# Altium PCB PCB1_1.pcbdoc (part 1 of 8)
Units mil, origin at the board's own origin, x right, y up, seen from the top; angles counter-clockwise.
Board outline 3937.01 x 3346.46 mil, 6 copper layers (Top Layer, Signal-1, SIG, POWER, Signal-4, Bottom Layer), stack 60.565 mil thick; 256 components, 201 nets, 1360 pads, 815 vias.
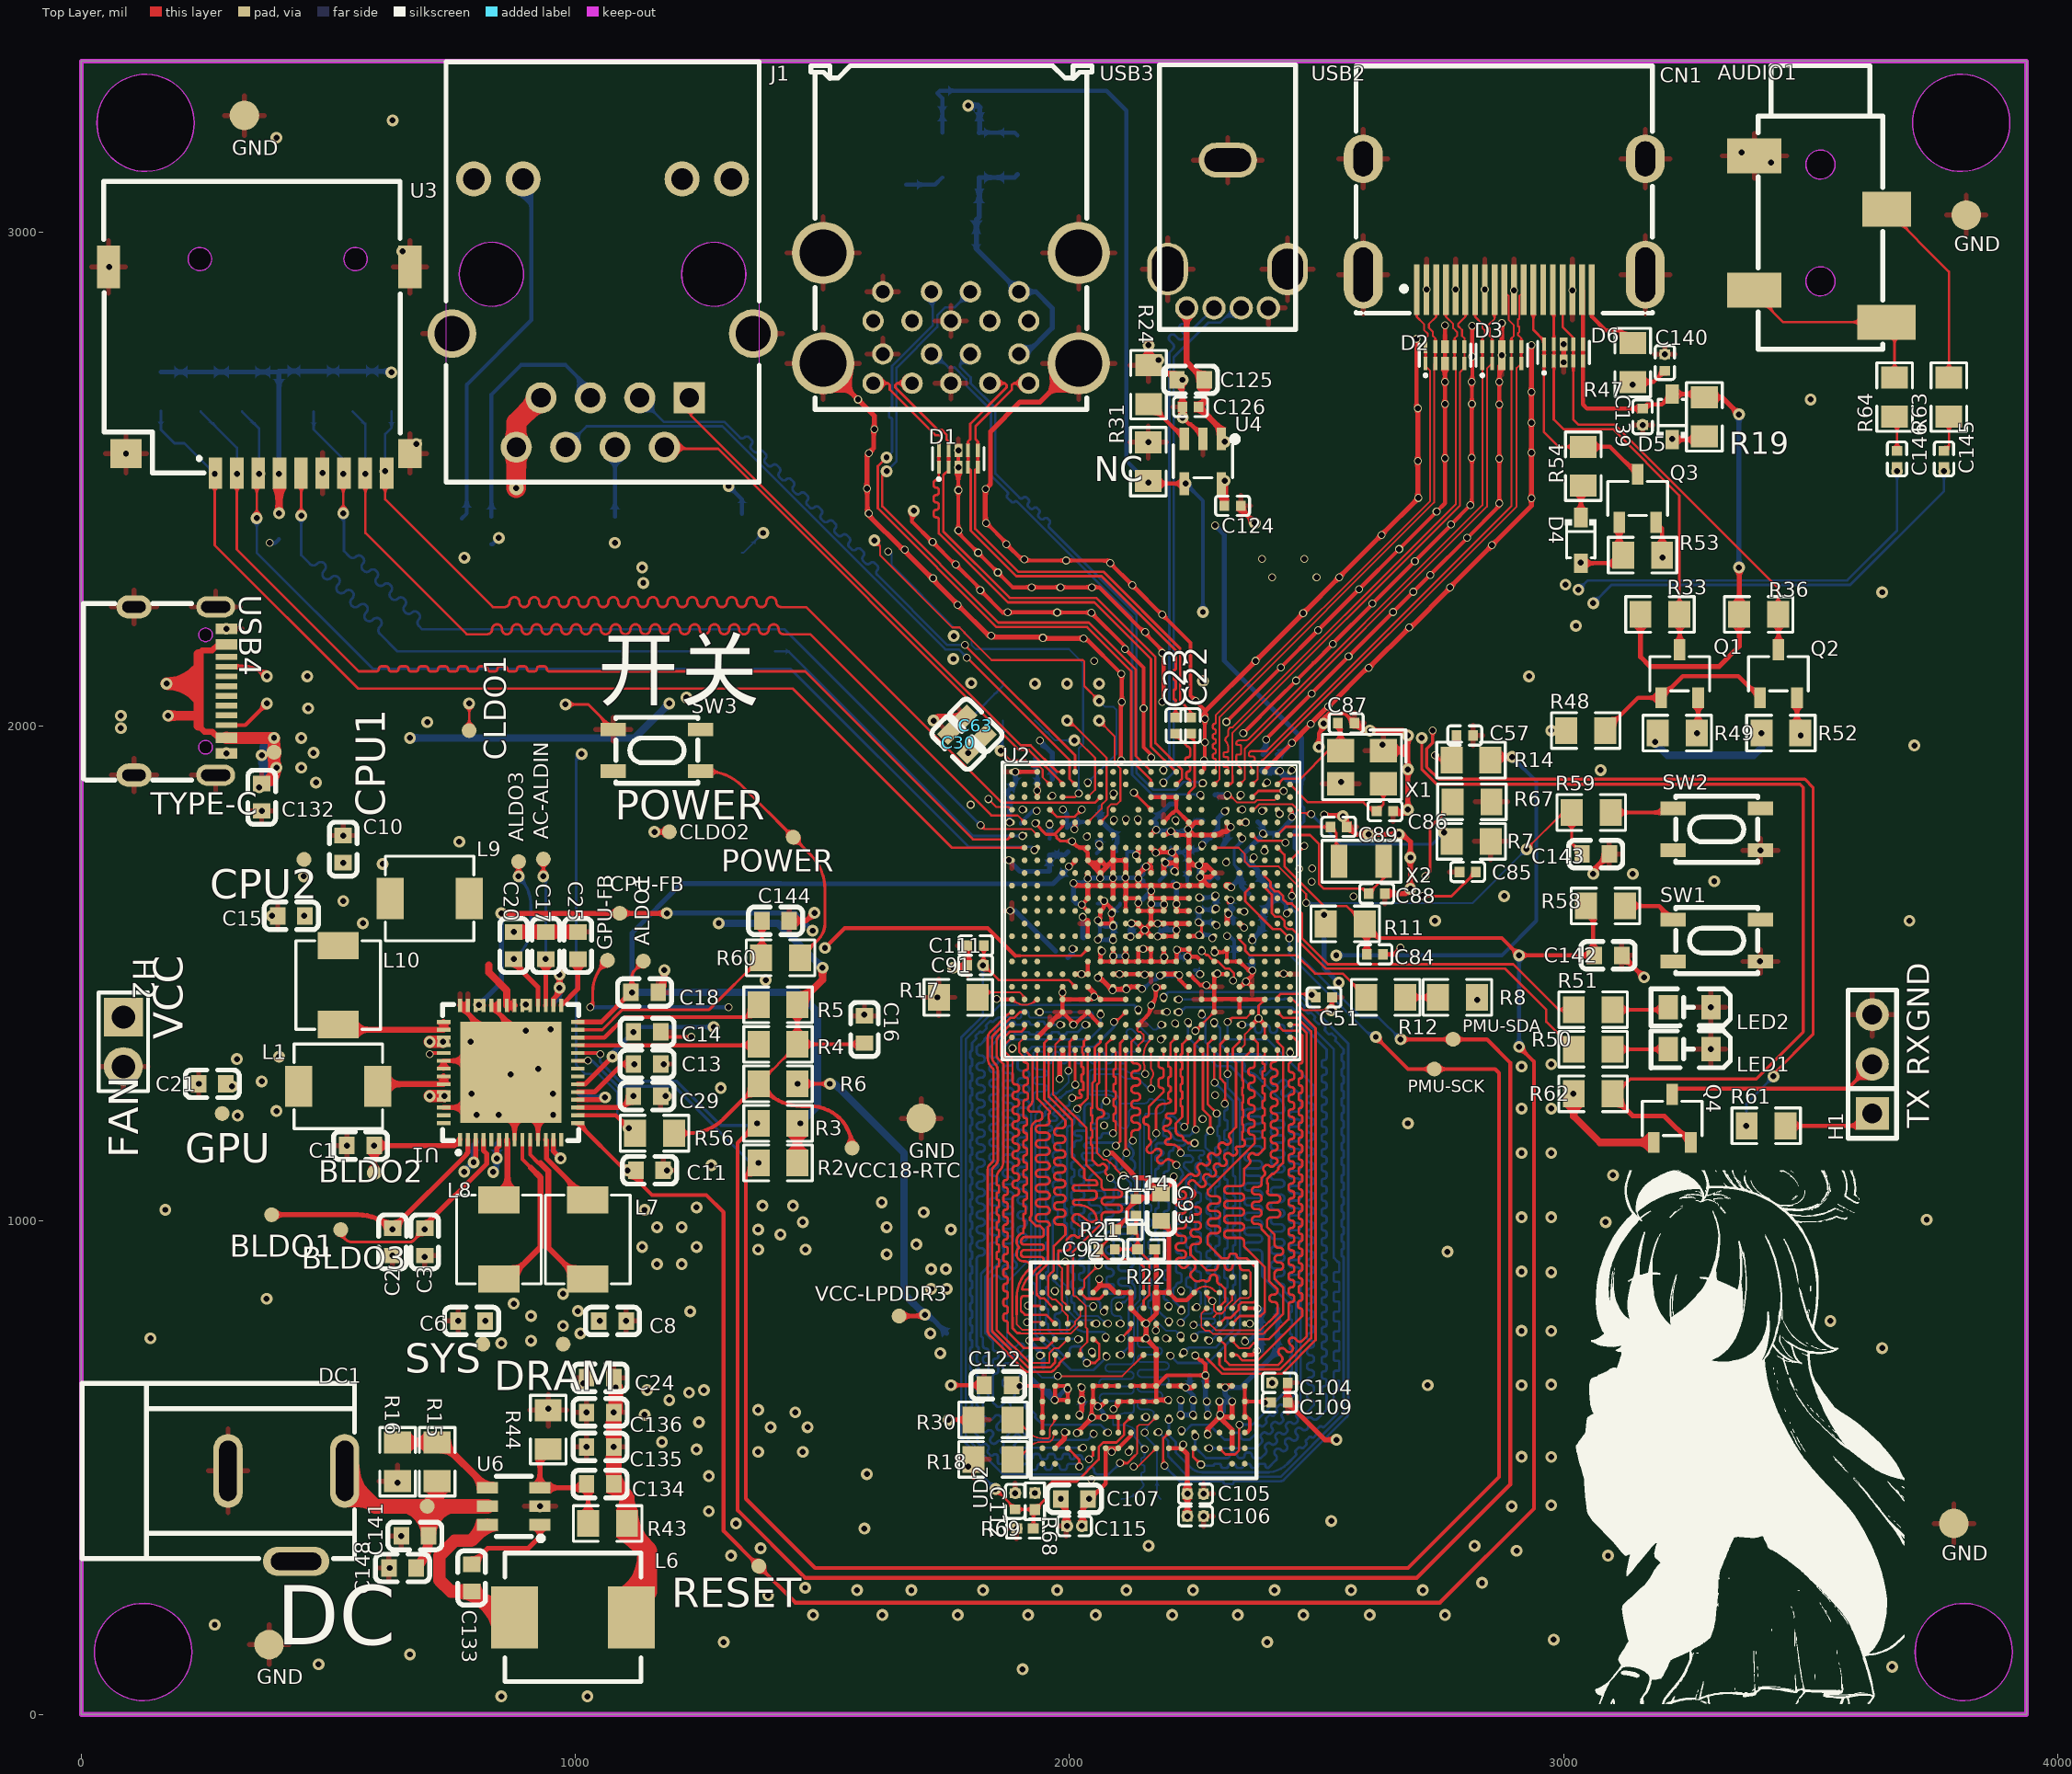
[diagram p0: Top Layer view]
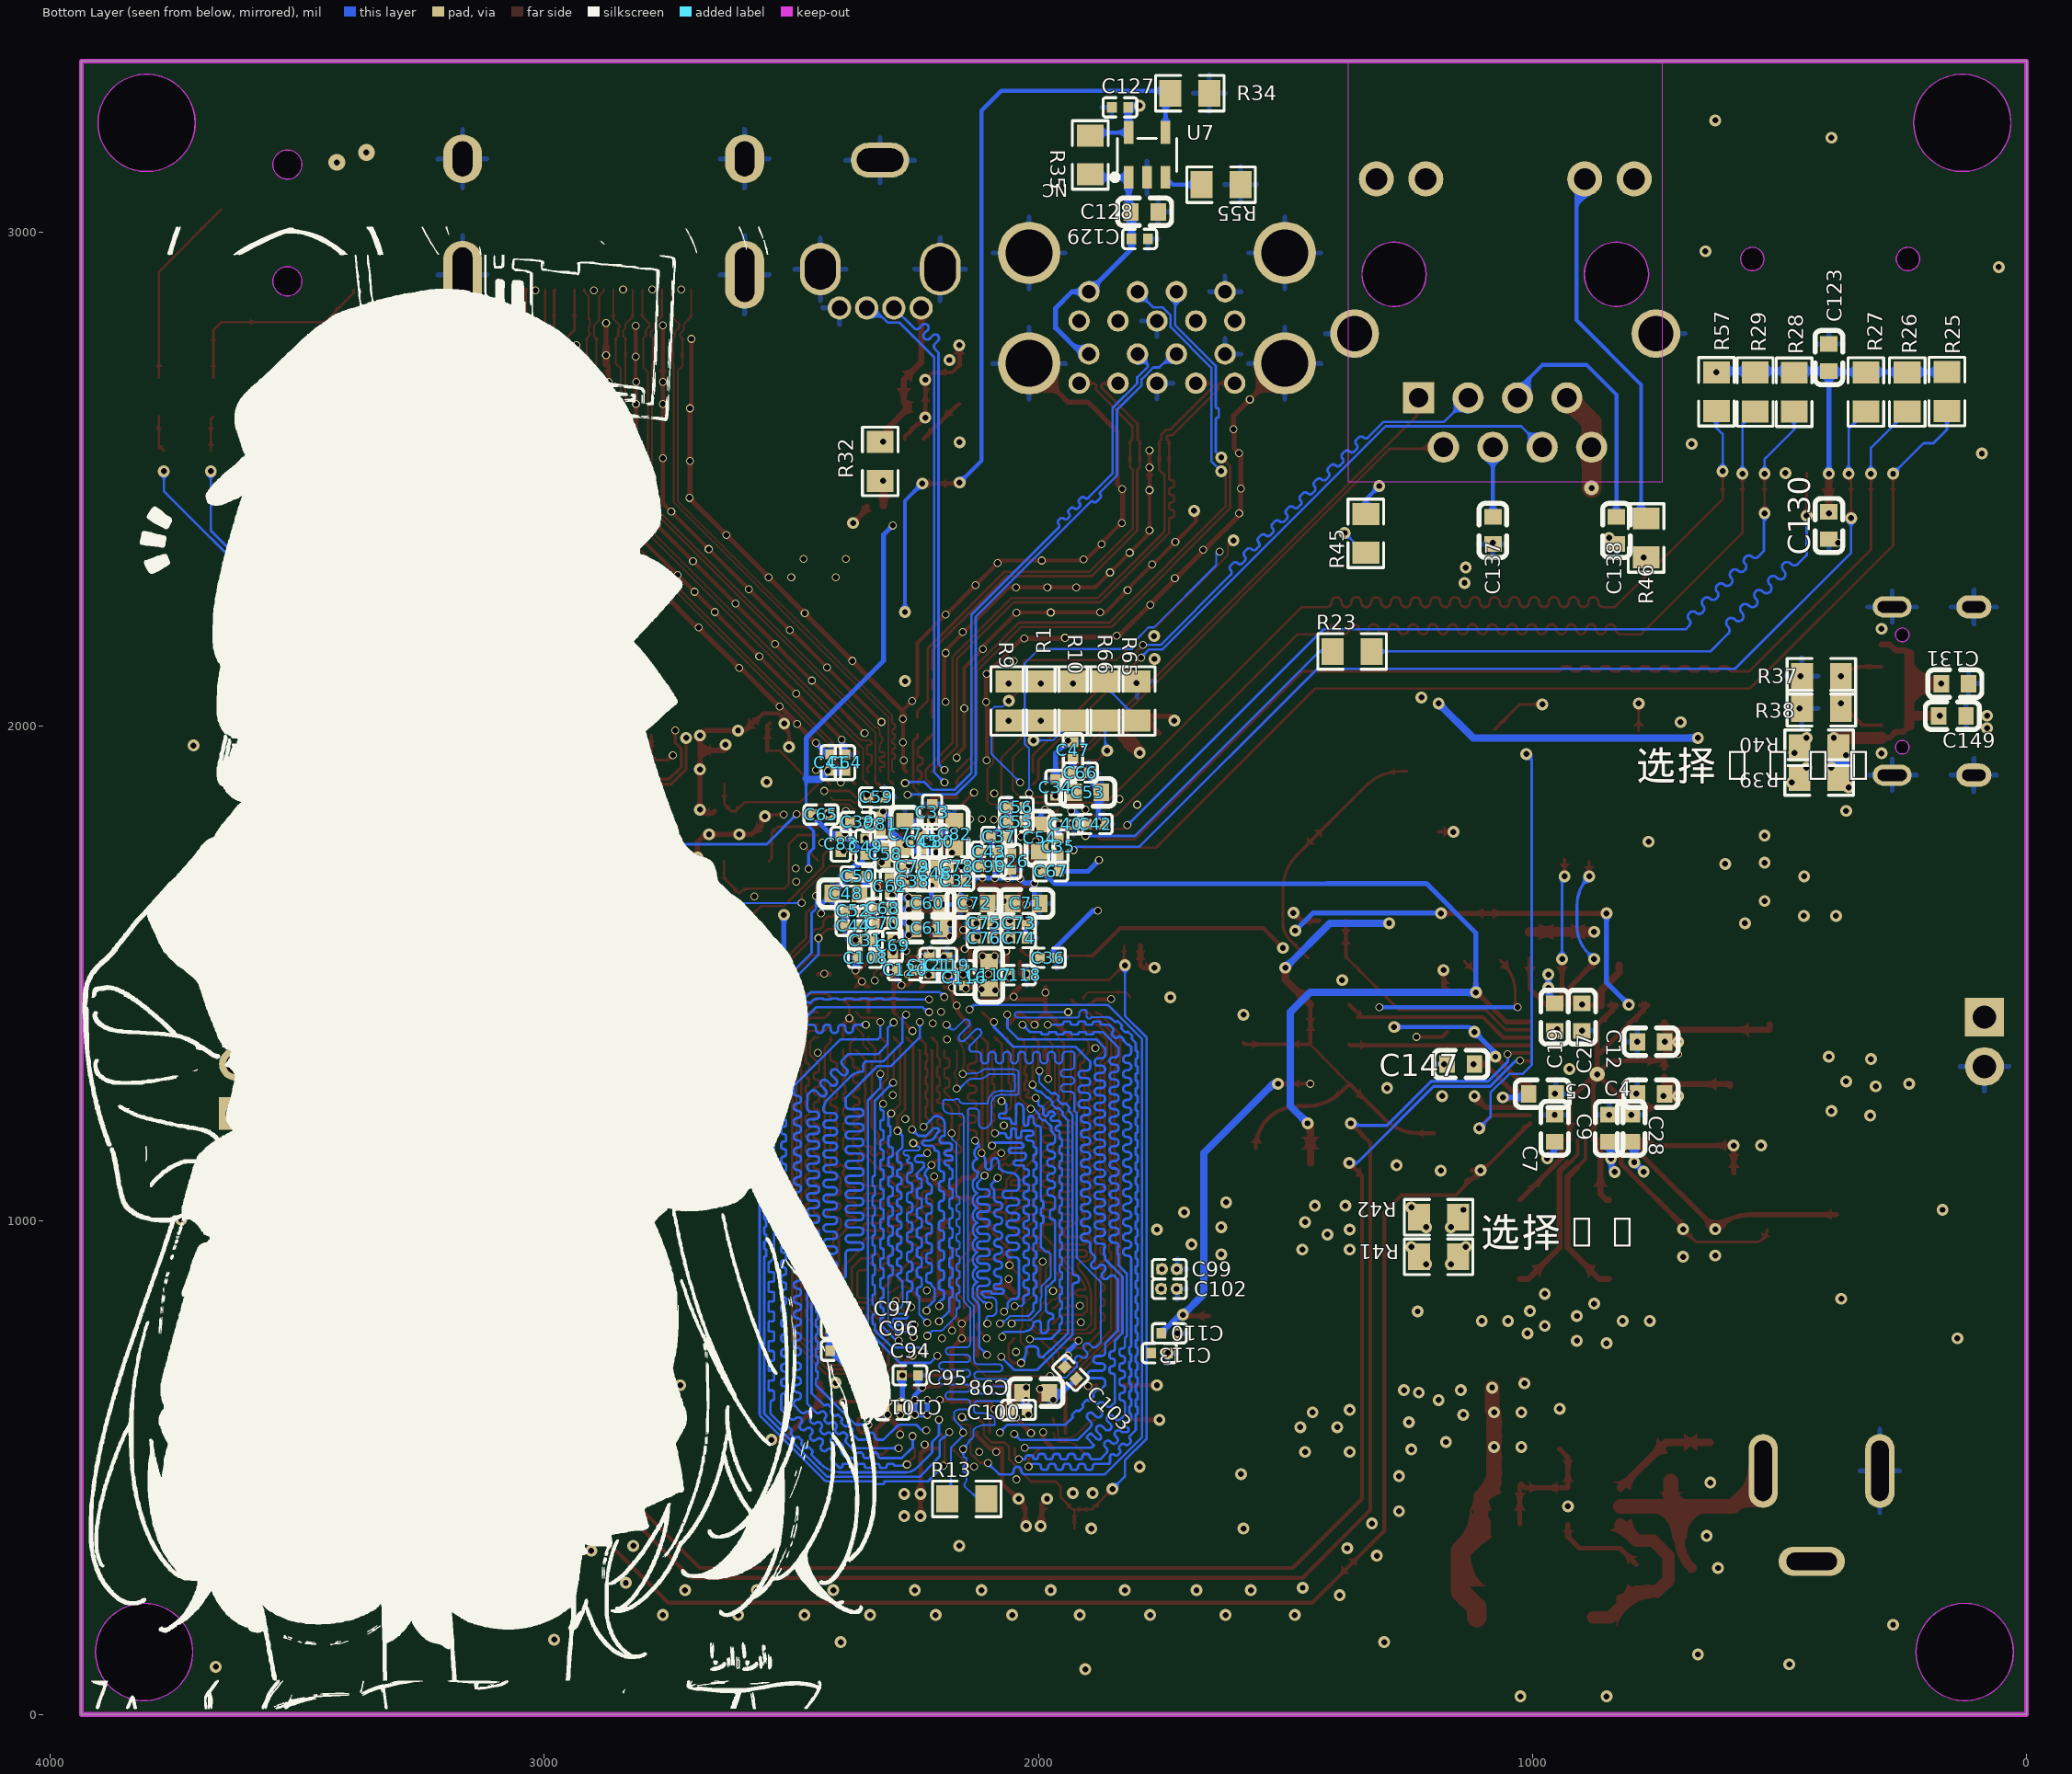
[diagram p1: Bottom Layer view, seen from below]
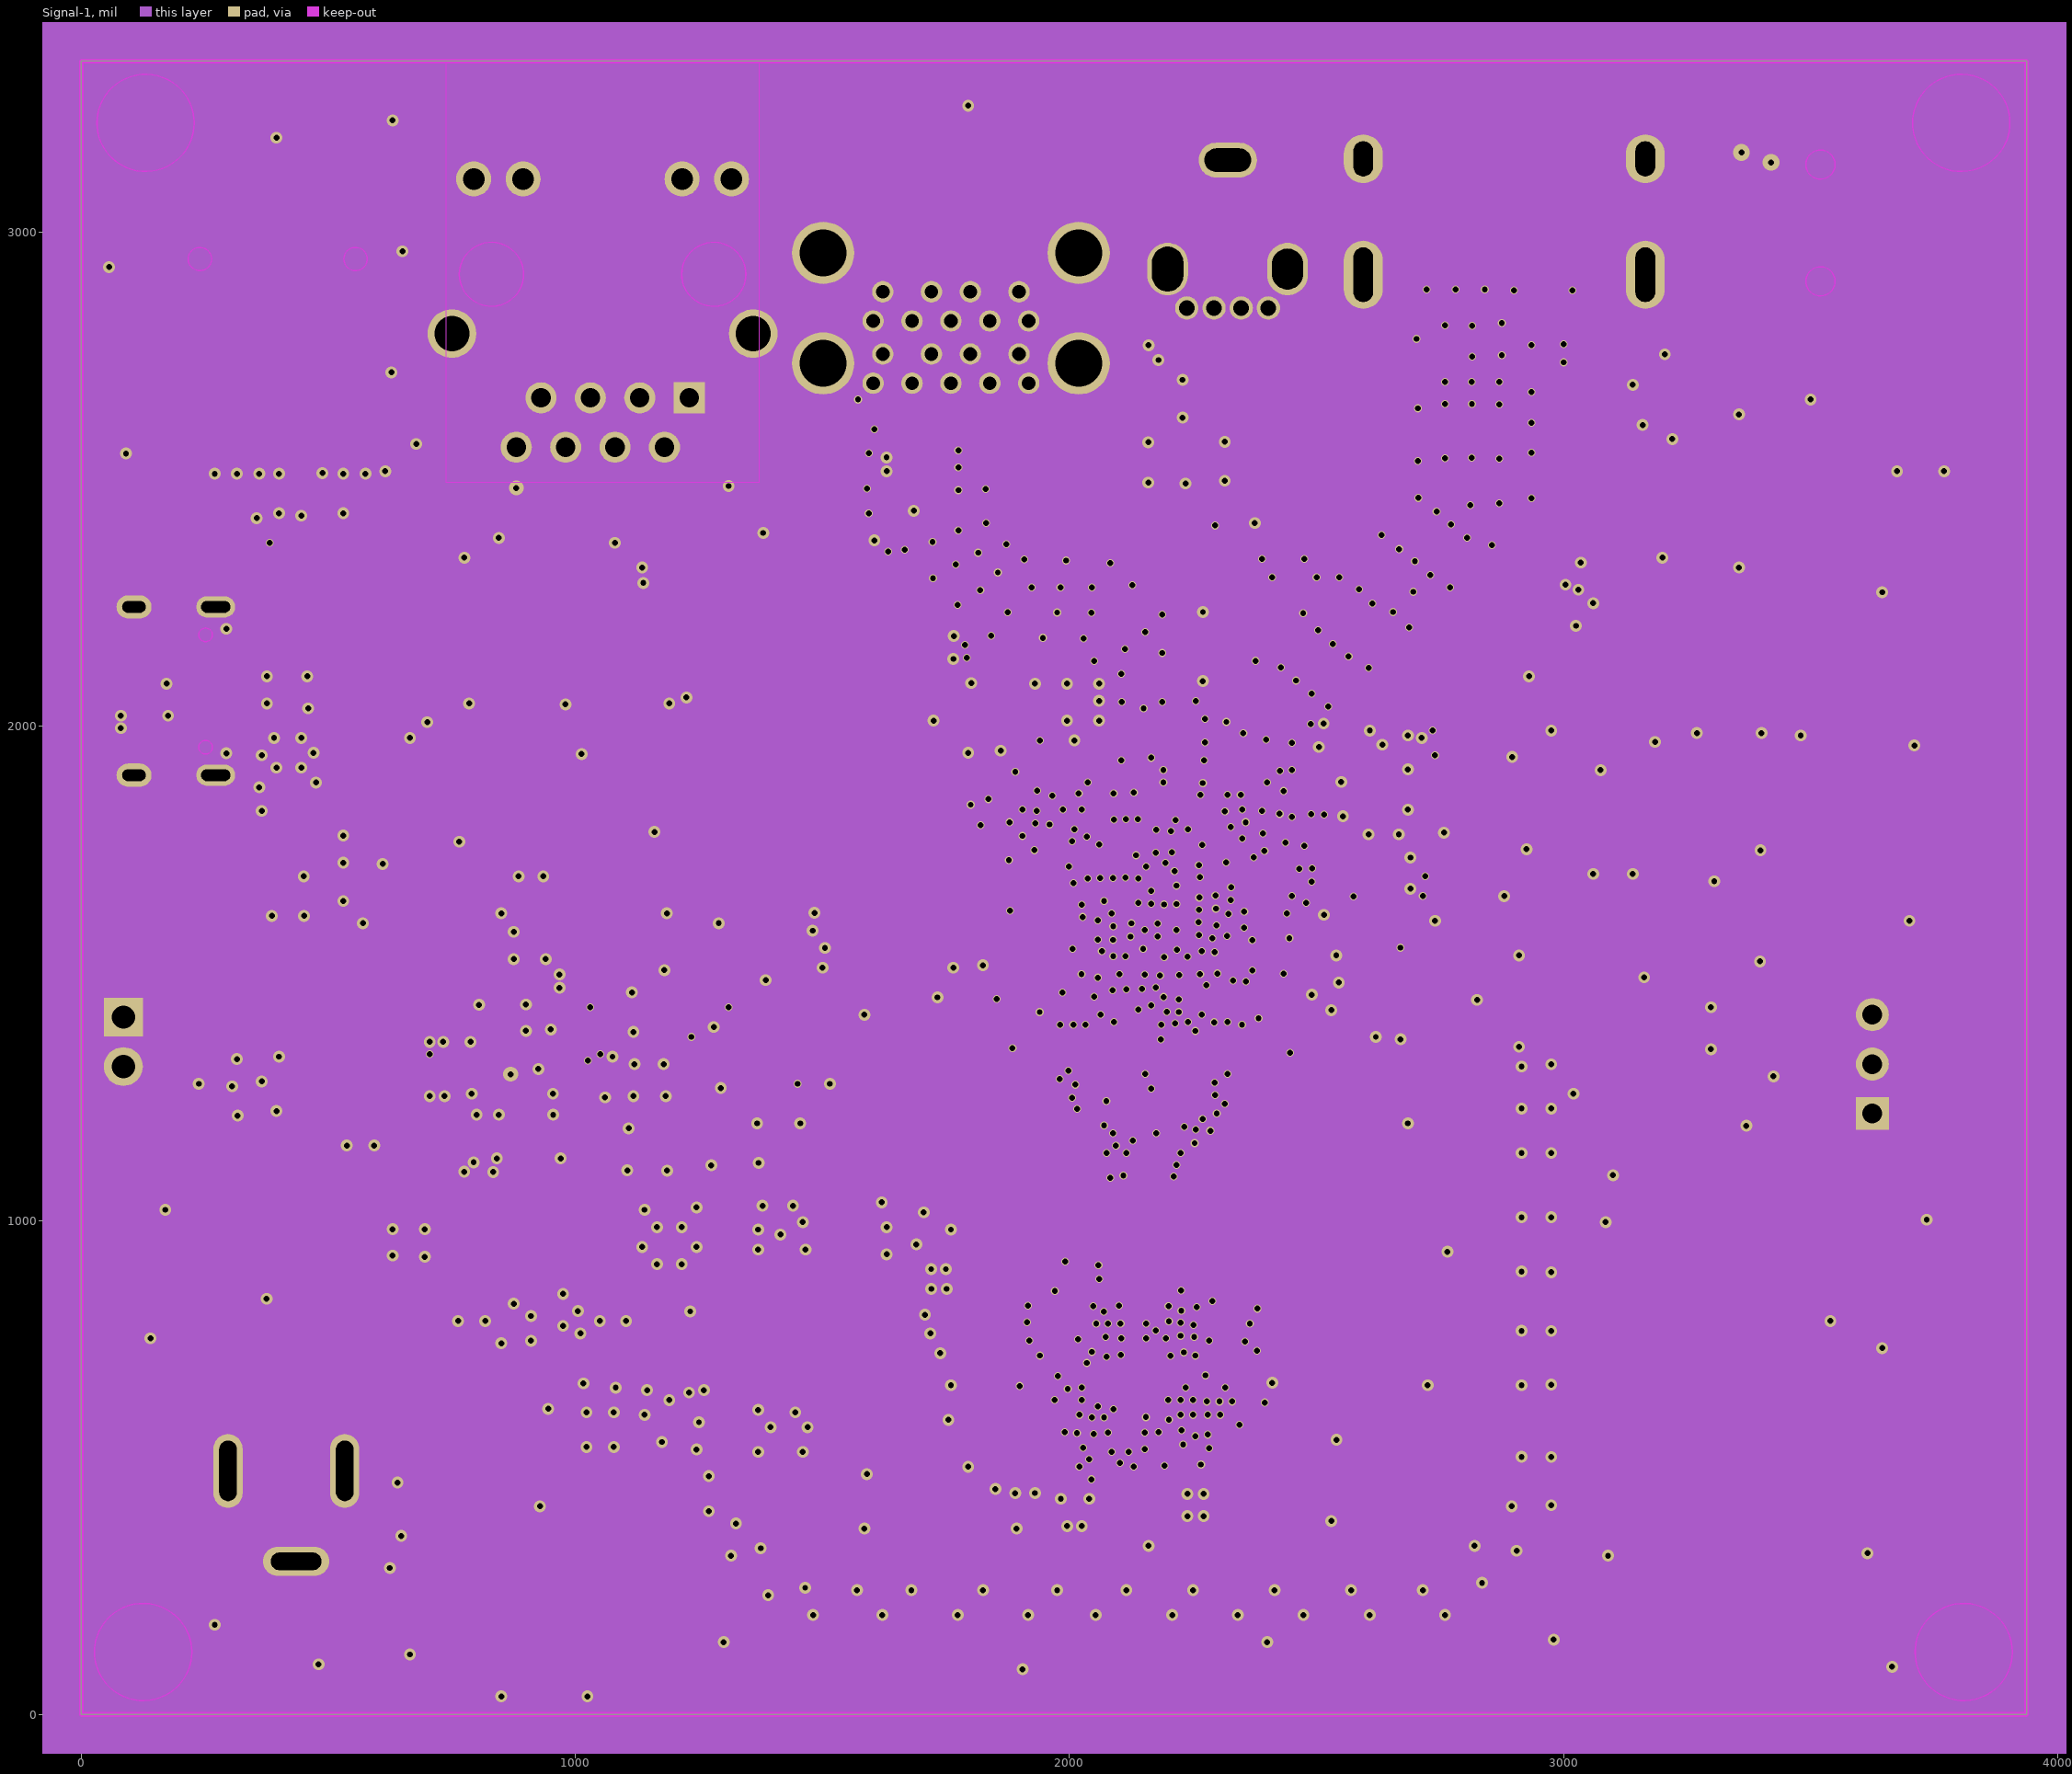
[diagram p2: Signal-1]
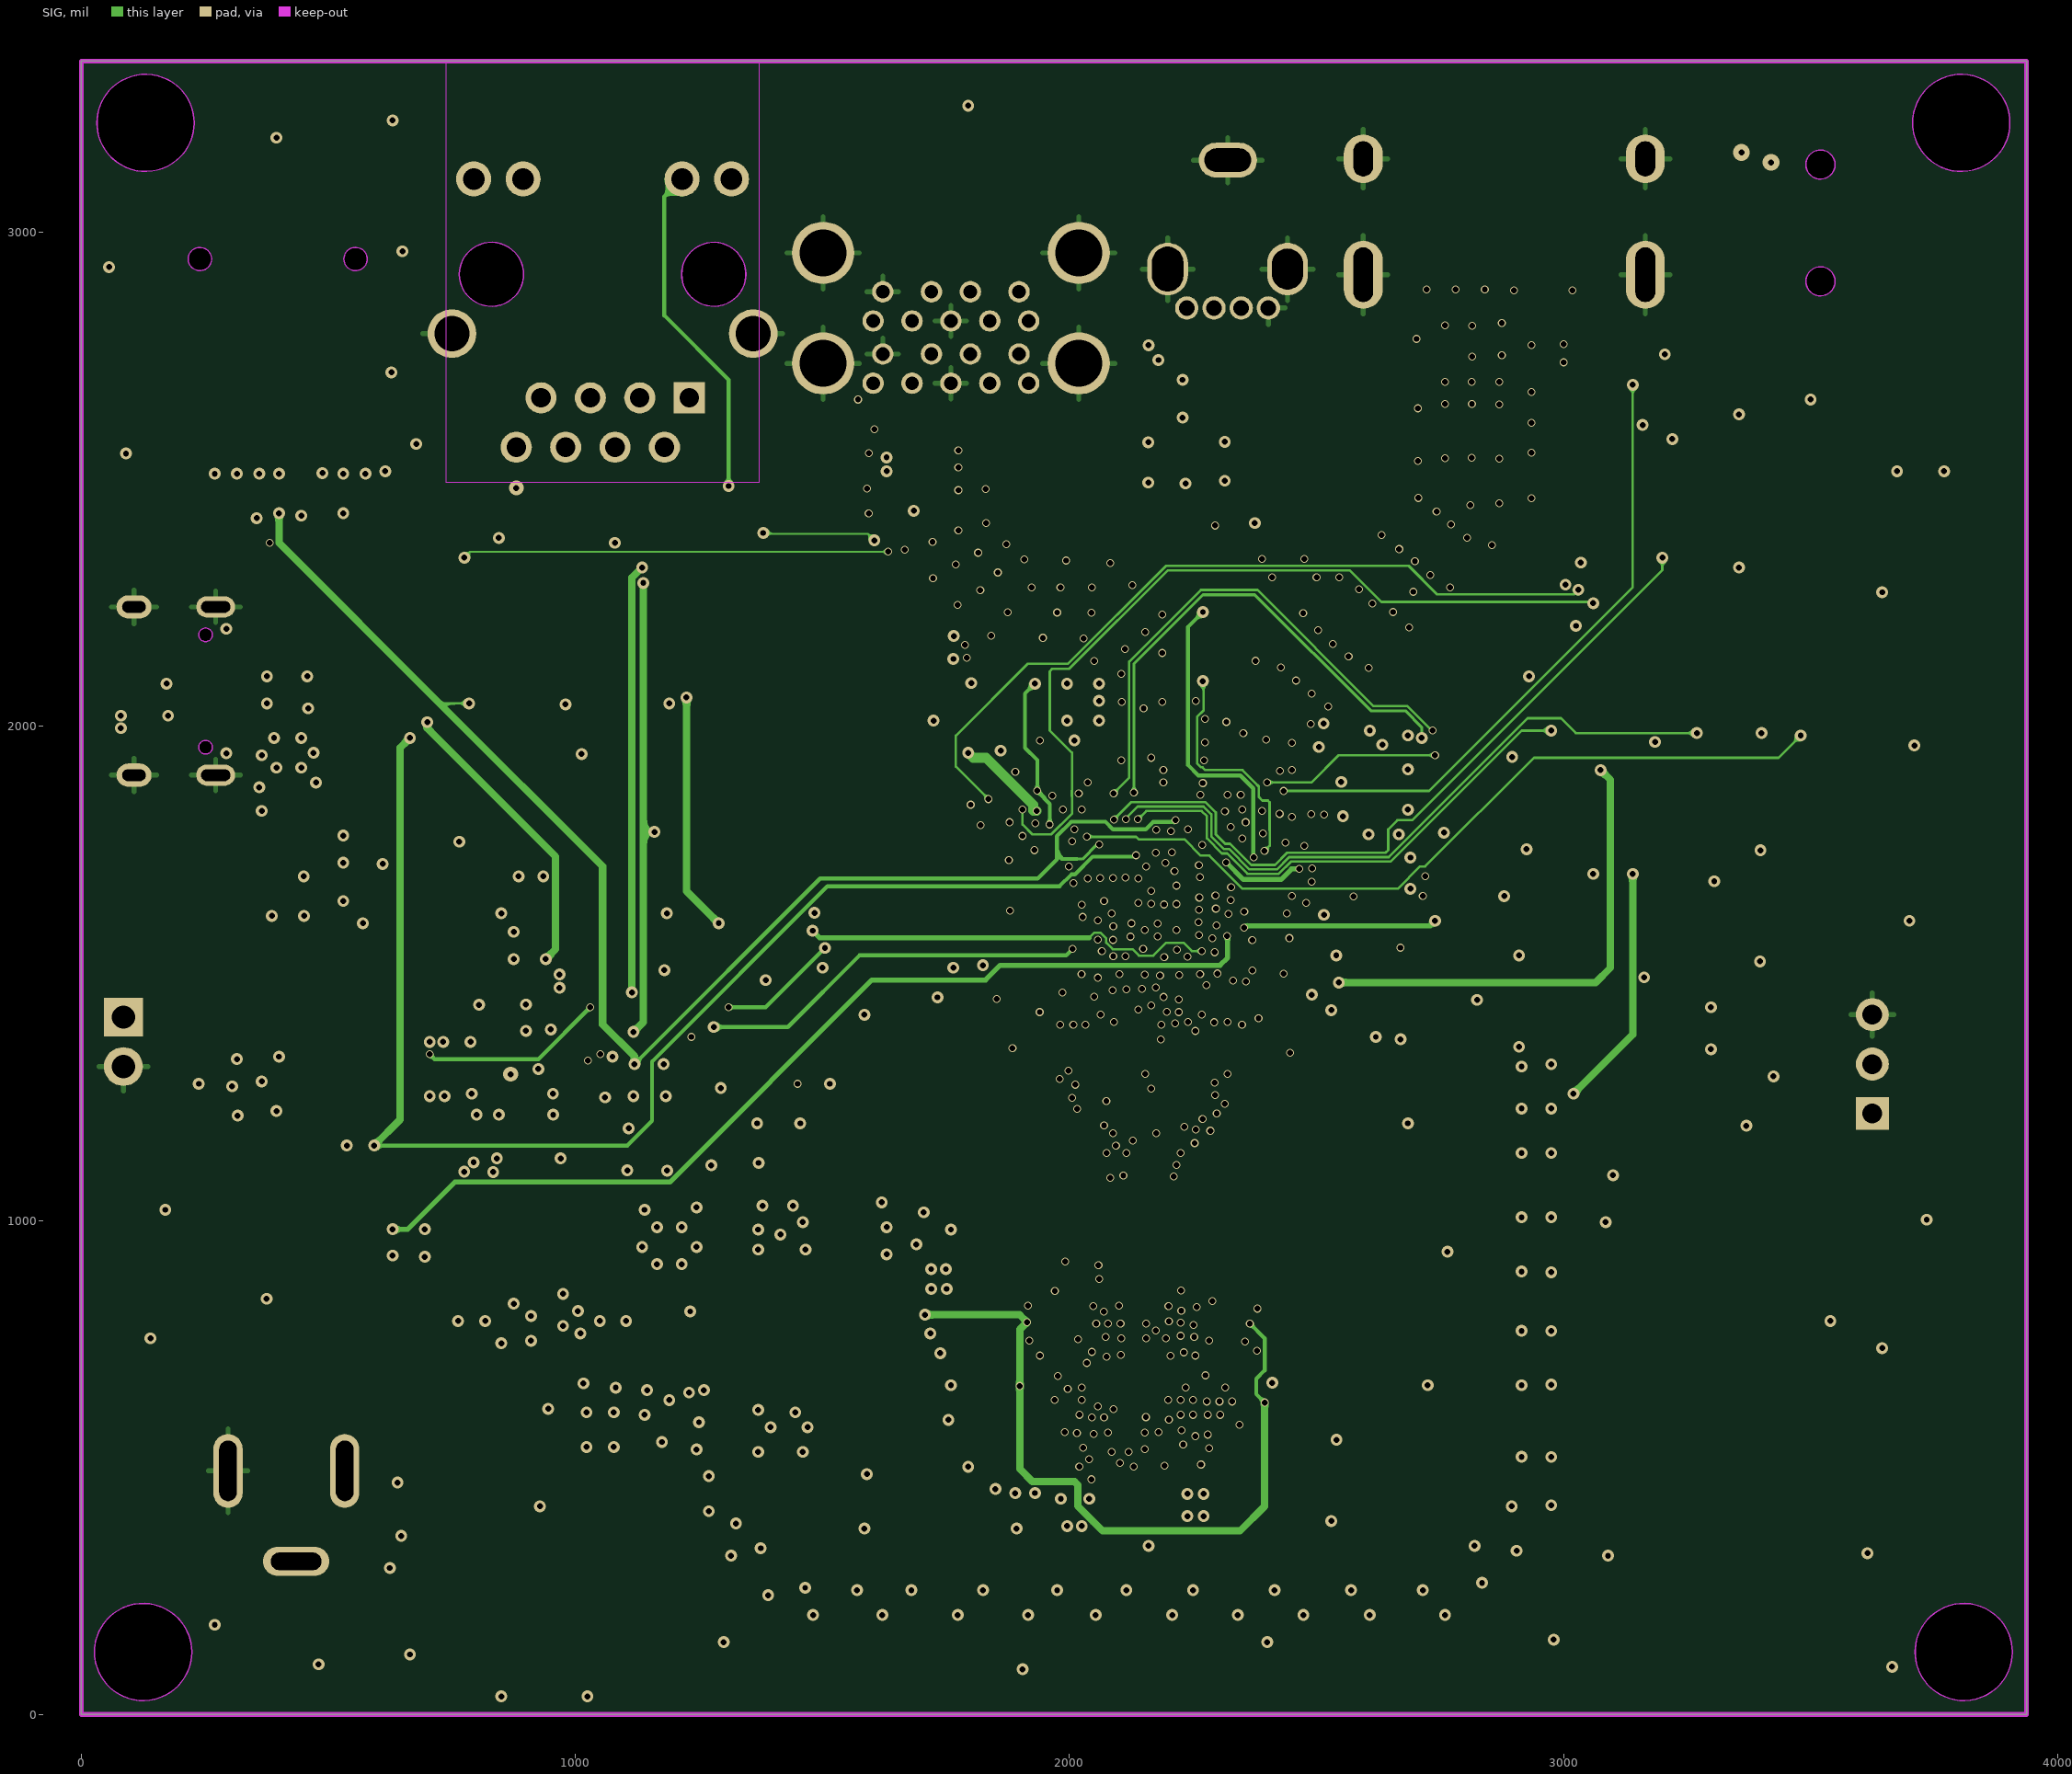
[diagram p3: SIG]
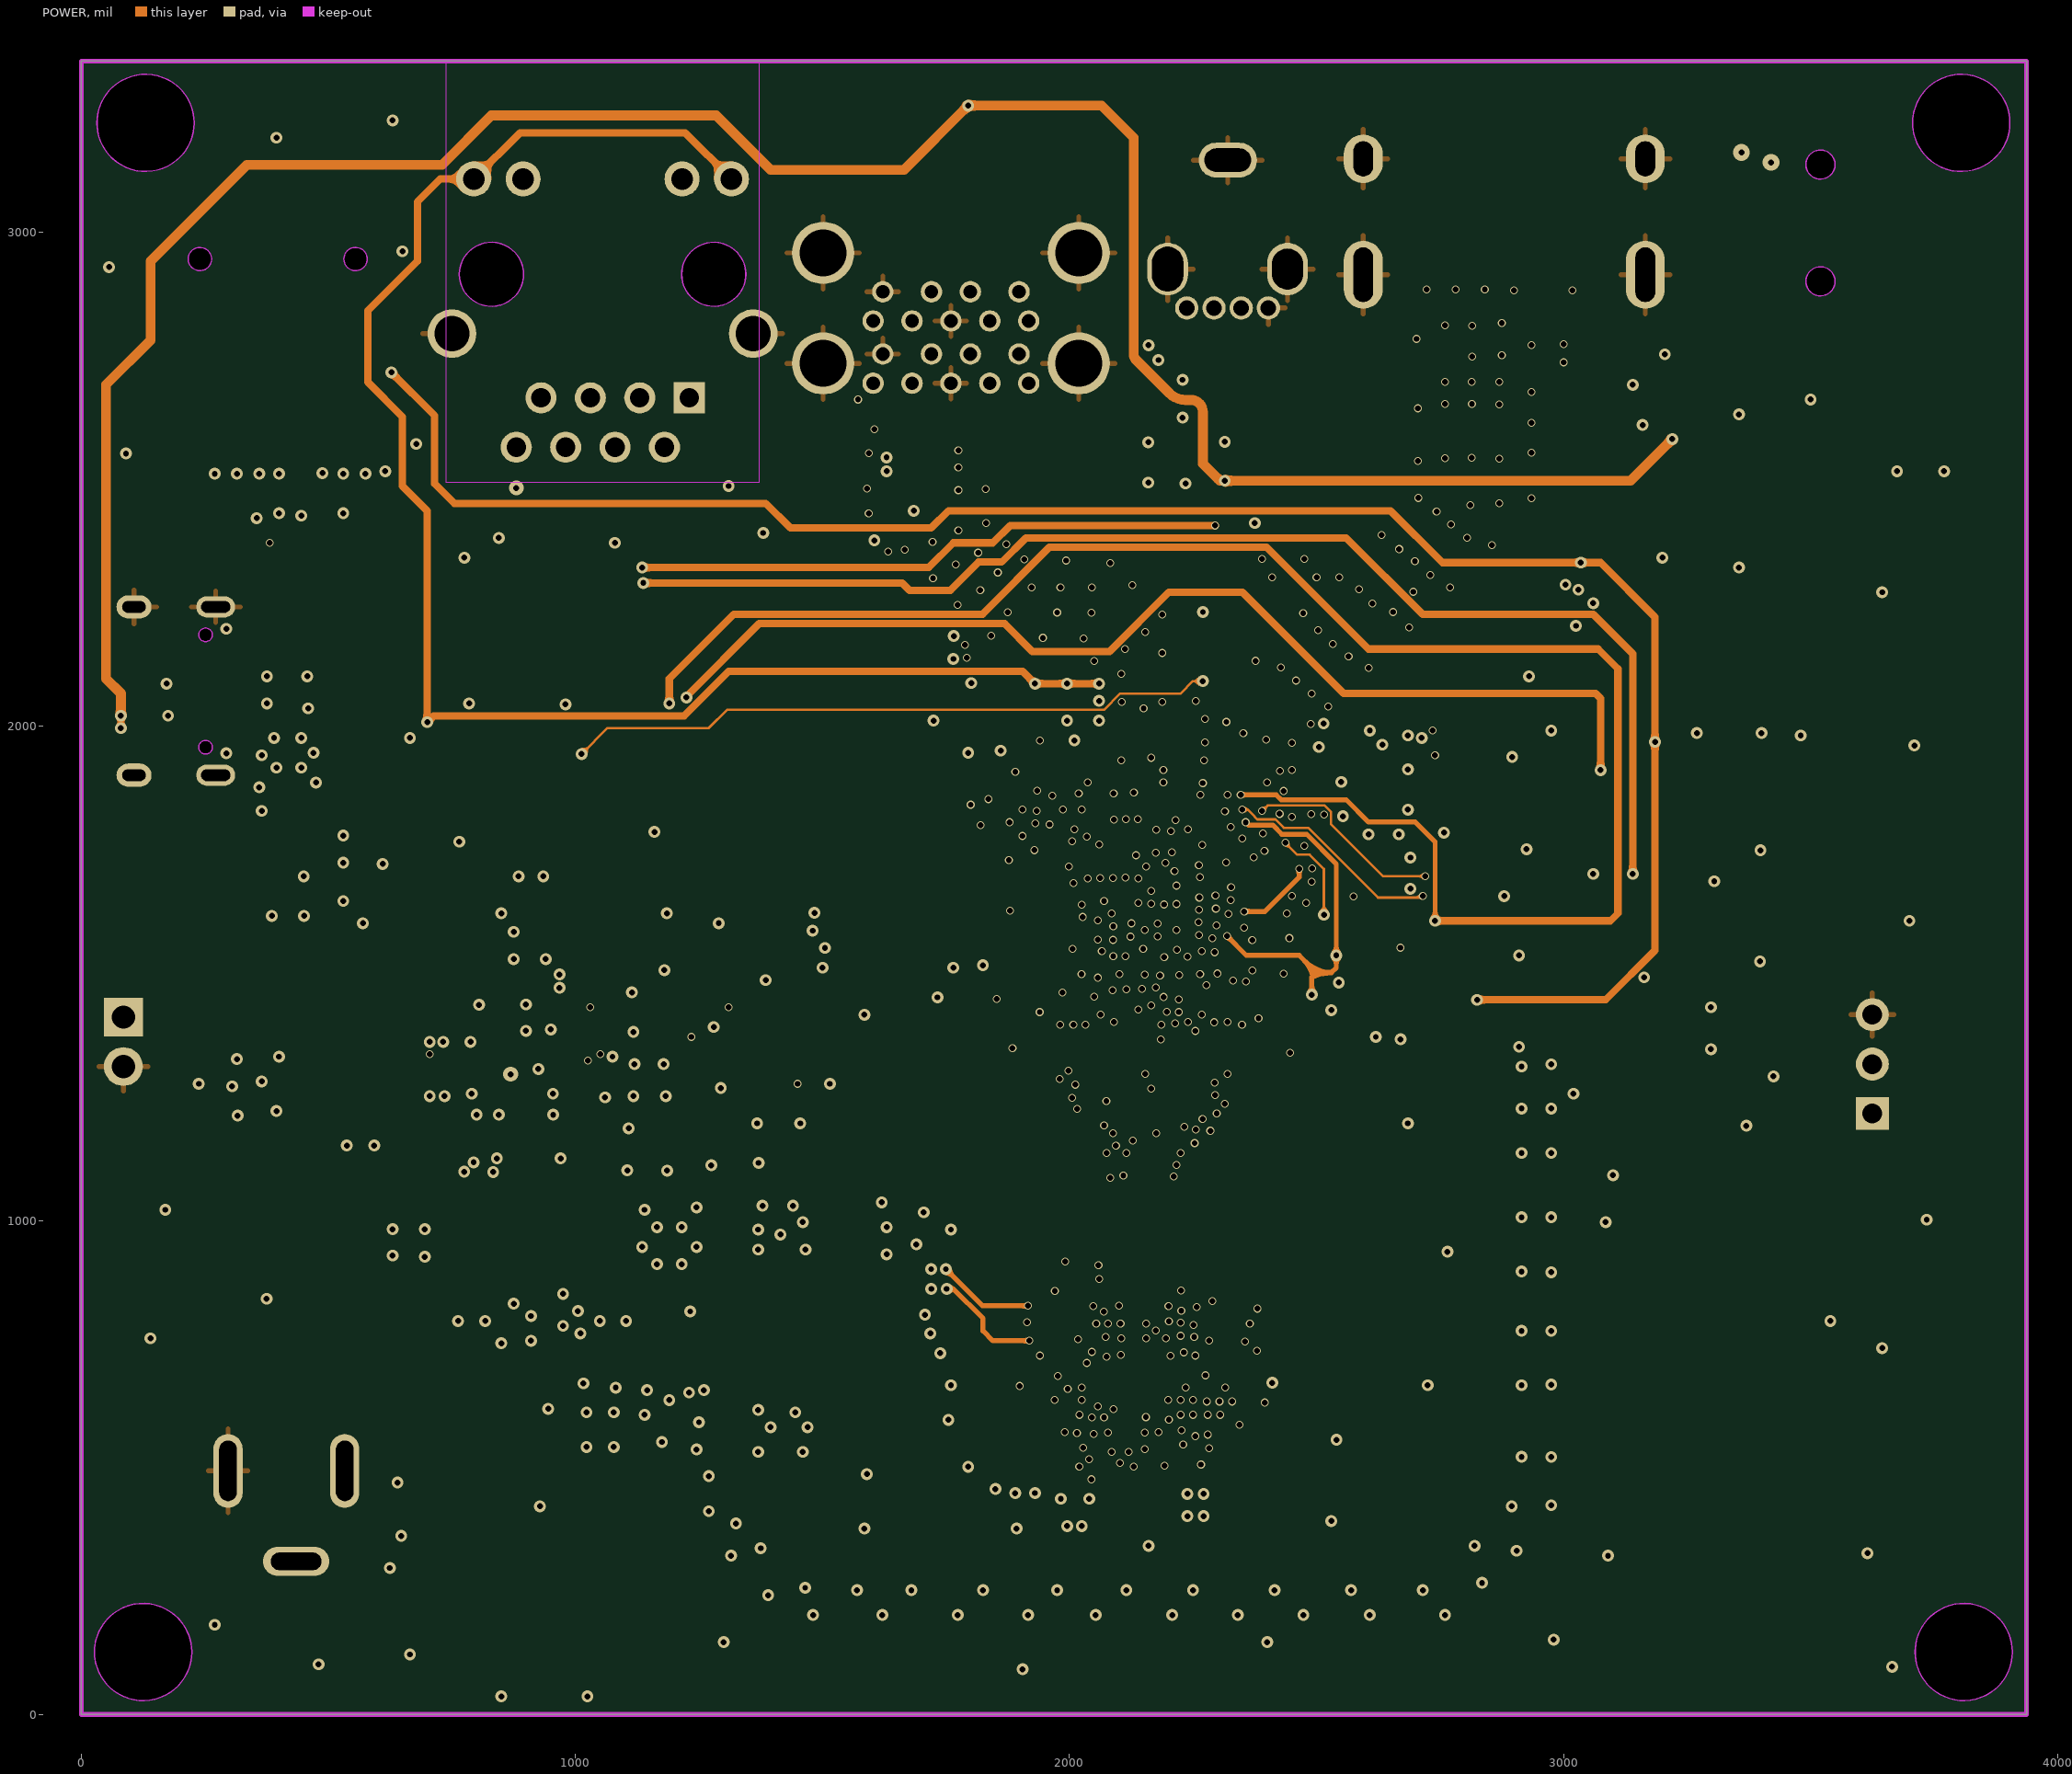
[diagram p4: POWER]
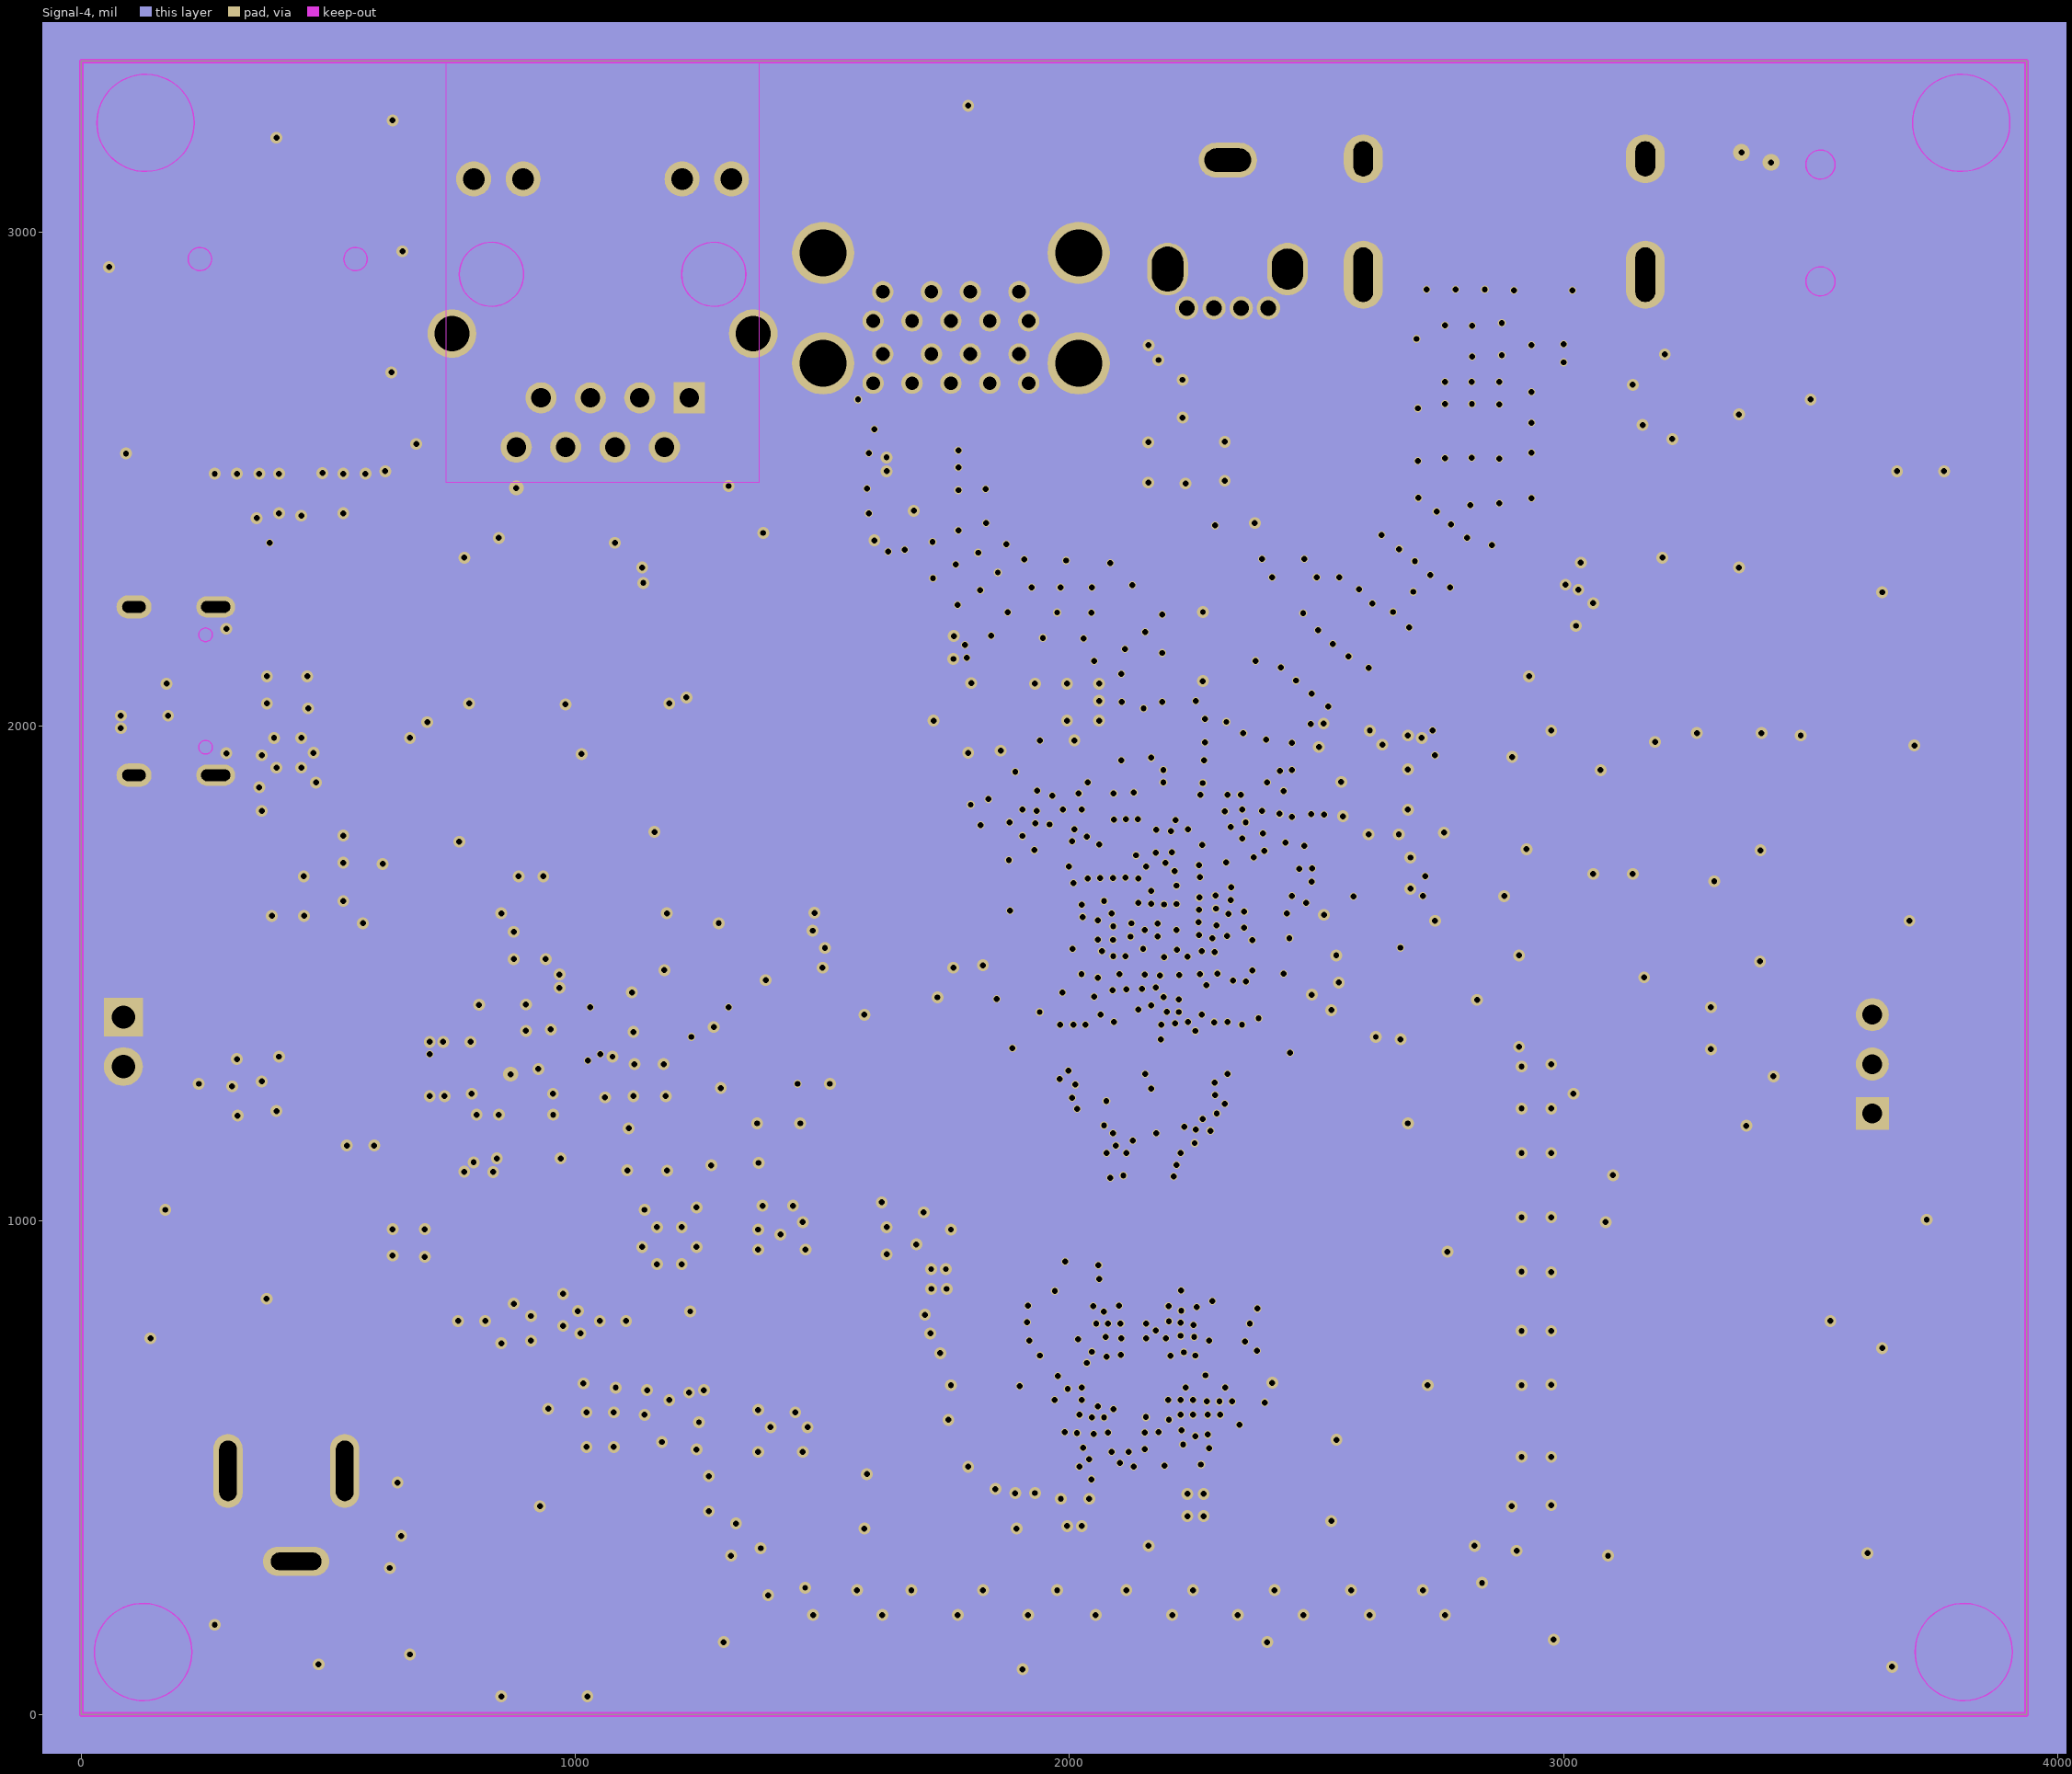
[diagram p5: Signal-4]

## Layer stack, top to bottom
Top Layer: signal copper 1.378
Dielectric1: surface 3.913, 3313 RC57% 4.2mil, Dk 0
Signal-1: signal copper 0.598
Dielectric2: surface 21.654, 0.55mm H/H No copper, Dk 0
SIG: signal copper 0.598
Dielectric3: surface 4.283, 2116 RC54% 4.9mil, Dk 0
POWER: signal copper 0.598
Dielectric4: surface 21.654, 0.55mm H/H No copper, Dk 0
Signal-4: signal copper 0.598
Dielectric5: surface 3.913, 3313 RC57% 4.2mil, Dk 0
Bottom Layer: signal copper 1.378

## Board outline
0,3346.46 0,0 3937.01,0 3937.01,3346.46
cut-out: 228.43,3221.46 cw(c130,3221.46) 31.57,3221.46 cw(c130,3221.46)
cut-out: 223.43,126.46 cw(c125,126.46) 26.57,126.46 cw(c125,126.46)
cut-out: 3908.43,126.46 cw(c3810,126.46) 3711.57,126.46 cw(c3810,126.46)
cut-out: 3903.43,3221.46 cw(c3805,3221.46) 3706.57,3221.46 cw(c3805,3221.46)

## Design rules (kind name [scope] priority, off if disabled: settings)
BoardOutlineClearance copperThickness2oz_1 [All] p2 off: genericclearance=7.99 ignorepadtopadclearanceinfootprint=FALSE except(0: Arc-SplitContinuation Track-SplitContinuation SMDPad-SplitContinuation THPad-SplitContinuation Via-SplitContinuation Fill-SplitContinuation Region-SplitContinuation Poly-SplitContinuation Text-SplitContinuation Hole-SplitContinuation; 5.98: Arc-CutoutEdge SMDPad-CutoutEdge THPad-CutoutEdge Via-CutoutEdge Fill-CutoutEdge Region-CutoutEdge Text-CutoutEdge; 6.93: Hole-OutlineEdge Hole-CutoutEdge; 10: Poly-OutlineEdge Poly-CutoutEdge; 11.81: Arc-OutlineEdge Track-OutlineEdge SMDPad-OutlineEdge THPad-OutlineEdge Via-OutlineEdge Fill-OutlineEdge Region-OutlineEdge Text-OutlineEdge Track-CutoutEdge)
BoardOutlineClearance copperThickness1oz_1 [All] p4: genericclearance=4 ignorepadtopadclearanceinfootprint=FALSE except(0: Arc-SplitContinuation Track-SplitContinuation SMDPad-SplitContinuation THPad-SplitContinuation Via-SplitContinuation Fill-SplitContinuation Region-SplitContinuation Poly-SplitContinuation Text-SplitContinuation Hole-SplitContinuation; 6: SMDPad-CutoutEdge THPad-CutoutEdge Via-CutoutEdge Fill-CutoutEdge Region-CutoutEdge Text-CutoutEdge; 6.93: Hole-OutlineEdge Hole-CutoutEdge; 10: Poly-OutlineEdge Poly-CutoutEdge; 11.8: Arc-OutlineEdge Track-OutlineEdge SMDPad-OutlineEdge THPad-OutlineEdge Via-OutlineEdge Fill-OutlineEdge Region-OutlineEdge Text-OutlineEdge; 11.81: Arc-CutoutEdge Track-CutoutEdge)
Clearance copperThickness2oz [All] p1 off: gap=7.99 ignorepadtopadclearanceinfootprint=FALSE except(5.98: SMDPad-Track SMDPad-SMDPad THPad-Track SMDPad-THPad THPad-THPad Track-Via SMDPad-Via THPad-Via Via-Via Fill-Track Region-Track Fill-SMDPad Region-SMDPad Fill-THPad Region-THPad Fill-Via Region-Via Fill-Fill Fill-Region Region-Region Arc-Track Arc-SMDPad Arc-THPad Arc-Via Fill-Arc Region-Arc Arc-Arc Text-Track SMDPad-Text Text-THPad Text-Via Fill-Text Region-Text Arc-Text Text-Text; 6.93: Hole-Track Hole-SMDPad Hole-THPad Hole-Via Fill-Hole Region-Hole Hole-Arc Hole-Text; 10: Poly-Track Poly-SMDPad Poly-THPad Poly-Via Poly-Fill Poly-Region Poly-Poly Poly-Arc Poly-Text Poly-Hole)
Clearance copperThickness1oz [All] p3: gap=4 ignorepadtopadclearanceinfootprint=FALSE except(3: SMDPad-Track; 3.5: SMDPad-SMDPad THPad-Track SMDPad-THPad Track-Via; 4.5: Poly-Via Hole-SMDPad Poly-Hole; 5: Hole-THPad; 6: Poly-SMDPad Poly-THPad Poly-Fill Poly-Region Poly-Poly Arc-Track Arc-SMDPad Arc-THPad Arc-Via Fill-Arc Region-Arc Arc-Arc Text-Track SMDPad-Text Text-THPad Text-Via Fill-Text Region-Text Arc-Text Text-Text Hole-Via; 6.93: Fill-Hole Region-Hole Hole-Arc Hole-Text; 10: Fill-Track Region-Track Poly-Track Poly-Arc Poly-Text)
DiffPairsRouting differentialPair [All] p1: maxlimit=6 minlimit=6 mostfreqgap=6 toplayer_minwidth=3.5 toplayer_prefwidth=10 toplayer_maxwidth=100 toplayer_mingap=4 toplayer_prefgap=6 toplayer_maxgap=6 midlayer1_minwidth=5 midlayer1_prefwidth=10 midlayer1_maxwidth=100 midlayer1_mingap=6 midlayer1_prefgap=6 midlayer1_maxgap=6 midlayer2_minwidth=5 midlayer2_prefwidth=10 midlayer2_maxwidth=100 midlayer2_mingap=6 midlayer2_prefgap=6 midlayer2_maxgap=6 midlayer3_minwidth=5 midlayer3_prefwidth=10 midlayer3_maxwidth=100 midlayer3_mingap=6 midlayer3_prefgap=6 midlayer3_maxgap=6 midlayer4_minwidth=5 midlayer4_prefwidth=10 midlayer4_maxwidth=100 midlayer4_mingap=6 midlayer4_prefgap=6 midlayer4_maxgap=6 bottomlayer_minwidth=3.5 bottomlayer_prefwidth=10 bottomlayer_maxwidth=100 bottomlayer_mingap=4 bottomlayer_prefgap=6 bottomlayer_maxgap=6 maxuncoupledlength=10
HoleToHoleClearance otherClearance [All] p1: gap=11.81 allowstackedmicrovias=TRUE
Length netLength [All] p1: minlimit=0 maxlimit=0
MatchedLengths netLengthTolerance [All] p1: tolerance=1000
PasteMaskExpansion pasteMaskExpansion [All] p1: expansion=0
PlaneConnect "innerPlane_Top Layer" [(OnLayer('Top Layer'))] p1: planeconnectstyle=Relief reliefexpansion=20 reliefentries=4 reliefconductorwidth=10 reliefairgap=10
PlaneConnect "innerPlane_Bottom Layer" [(OnLayer('Bottom Layer'))] p2: planeconnectstyle=Relief reliefexpansion=20 reliefentries=4 reliefconductorwidth=10 reliefairgap=10
PlaneConnect "innerPlane_Mid Layer 1" [(OnLayer('Mid Layer 1'))] p3: planeconnectstyle=Relief reliefexpansion=20 reliefentries=4 reliefconductorwidth=10 reliefairgap=10
PlaneConnect innerPlane_SIG [(OnLayer('SIG'))] p4: planeconnectstyle=Relief reliefexpansion=20 reliefentries=4 reliefconductorwidth=10 reliefairgap=10
PlaneConnect innerPlane [All] p5: planeconnectstyle=Direct reliefexpansion=20 reliefentries=4 reliefconductorwidth=10 reliefairgap=10
PolygonConnect "copperRegion1_Top Layer" [(InNet('VCC-DRAM') OR InNet('VDD-SYS') OR InNet('VDD-CPU') OR InNet('VDD-GPU') OR InNet('USB-5V') OR InNet('DC-5V') OR InNet('LXD') OR InNet('LXE') OR InNet('LXA') OR InNet('LXB') OR InNet('LXC')) And OnLayer('Top Layer')] p1: connectstyle=Direct reliefconductorwidth=10 reliefentries=4 polygonreliefangle="90 Angle" airgapwidth=10 via.connectstyle=Relief via.reliefconductorwidth=10 via.reliefentries=4 via.polygonreliefangle="90 Angle" via.airgapwidth=10
PolygonConnect "copperRegion1_Bottom Layer" [(InNet('VCC-DRAM') OR InNet('VDD-SYS') OR InNet('VDD-CPU') OR InNet('VDD-GPU') OR InNet('USB-5V') OR InNet('DC-5V') OR InNet('LXD') OR InNet('LXE') OR InNet('LXA') OR InNet('LXB') OR InNet('LXC')) And OnLayer('Bottom Layer')] p2: connectstyle=Direct reliefconductorwidth=10 reliefentries=4 polygonreliefangle="90 Angle" airgapwidth=10 via.connectstyle=Relief via.reliefconductorwidth=10 via.reliefentries=4 via.polygonreliefangle="90 Angle" via.airgapwidth=10
PolygonConnect "copperRegion1_Mid Layer 1" [(InNet('VCC-DRAM') OR InNet('VDD-SYS') OR InNet('VDD-CPU') OR InNet('VDD-GPU') OR InNet('USB-5V') OR InNet('DC-5V') OR InNet('LXD') OR InNet('LXE') OR InNet('LXA') OR InNet('LXB') OR InNet('LXC')) And OnLayer('Mid Layer 1')] p3: connectstyle=Direct reliefconductorwidth=10 reliefentries=4 polygonreliefangle="90 Angle" airgapwidth=10 smdpad.connectstyle=Relief smdpad.reliefconductorwidth=10 smdpad.reliefentries=4 smdpad.polygonreliefangle="90 Angle" smdpad.airgapwidth=10 via.connectstyle=Relief via.reliefconductorwidth=10 via.reliefentries=4 via.polygonreliefangle="90 Angle" via.airgapwidth=10
PolygonConnect copperRegion1_SIG [(InNet('VCC-DRAM') OR InNet('VDD-SYS') OR InNet('VDD-CPU') OR InNet('VDD-GPU') OR InNet('USB-5V') OR InNet('DC-5V') OR InNet('LXD') OR InNet('LXE') OR InNet('LXA') OR InNet('LXB') OR InNet('LXC')) And OnLayer('SIG')] p4: connectstyle=Direct reliefconductorwidth=10 reliefentries=4 polygonreliefangle="90 Angle" airgapwidth=10 smdpad.connectstyle=Relief smdpad.reliefconductorwidth=10 smdpad.reliefentries=4 smdpad.polygonreliefangle="90 Angle" smdpad.airgapwidth=10 via.connectstyle=Relief via.reliefconductorwidth=10 via.reliefentries=4 via.polygonreliefangle="90 Angle" via.airgapwidth=10
PolygonConnect copperRegion1_POWER [(InNet('VCC-DRAM') OR InNet('VDD-SYS') OR InNet('VDD-CPU') OR InNet('VDD-GPU') OR InNet('USB-5V') OR InNet('DC-5V') OR InNet('LXD') OR InNet('LXE') OR InNet('LXA') OR InNet('LXB') OR InNet('LXC')) And OnLayer('POWER')] p5: connectstyle=Direct reliefconductorwidth=10 reliefentries=4 polygonreliefangle="90 Angle" airgapwidth=10 smdpad.connectstyle=Relief smdpad.reliefconductorwidth=10 smdpad.reliefentries=4 smdpad.polygonreliefangle="90 Angle" smdpad.airgapwidth=10 via.connectstyle=Relief via.reliefconductorwidth=10 via.reliefentries=4 via.polygonreliefangle="90 Angle" via.airgapwidth=10
PolygonConnect "copperRegion1_Mid Layer 4" [(InNet('VCC-DRAM') OR InNet('VDD-SYS') OR InNet('VDD-CPU') OR InNet('VDD-GPU') OR InNet('USB-5V') OR InNet('DC-5V') OR InNet('LXD') OR InNet('LXE') OR InNet('LXA') OR InNet('LXB') OR InNet('LXC')) And OnLayer('Mid Layer 4')] p6: connectstyle=Direct reliefconductorwidth=10 reliefentries=4 polygonreliefangle="90 Angle" airgapwidth=10 smdpad.connectstyle=Relief smdpad.reliefconductorwidth=10 smdpad.reliefentries=4 smdpad.polygonreliefangle="90 Angle" smdpad.airgapwidth=10 via.connectstyle=Relief via.reliefconductorwidth=10 via.reliefentries=4 via.polygonreliefangle="90 Angle" via.airgapwidth=10
PolygonConnect copperRegion1 [(InNet('VCC-DRAM') OR InNet('VDD-SYS') OR InNet('VDD-CPU') OR InNet('VDD-GPU') OR InNet('USB-5V') OR InNet('DC-5V') OR InNet('LXD') OR InNet('LXE') OR InNet('LXA') OR InNet('LXB') OR InNet('LXC'))] p7: connectstyle=Direct reliefconductorwidth=10 reliefentries=4 polygonreliefangle="90 Angle" airgapwidth=10 via.connectstyle=Relief via.reliefconductorwidth=10 via.reliefentries=4 via.polygonreliefangle="90 Angle" via.airgapwidth=10
PolygonConnect "copperRegion_Top Layer" [(InNet('GND')) And OnLayer('Top Layer')] p8: connectstyle=Relief reliefconductorwidth=10 reliefentries=4 polygonreliefangle="90 Angle" airgapwidth=10 via.connectstyle=Relief via.reliefconductorwidth=10 via.reliefentries=4 via.polygonreliefangle="90 Angle" via.airgapwidth=10
PolygonConnect "copperRegion_Bottom Layer" [(InNet('GND')) And OnLayer('Bottom Layer')] p9: connectstyle=Relief reliefconductorwidth=10 reliefentries=4 polygonreliefangle="90 Angle" airgapwidth=10 via.connectstyle=Relief via.reliefconductorwidth=10 via.reliefentries=4 via.polygonreliefangle="90 Angle" via.airgapwidth=10
PolygonConnect "copperRegion_Mid Layer 1" [(InNet('GND')) And OnLayer('Mid Layer 1')] p10: connectstyle=Relief reliefconductorwidth=10 reliefentries=4 polygonreliefangle="90 Angle" airgapwidth=10 smdpad.connectstyle=Relief smdpad.reliefconductorwidth=10 smdpad.reliefentries=4 smdpad.polygonreliefangle="90 Angle" smdpad.airgapwidth=10 via.connectstyle=Relief via.reliefconductorwidth=10 via.reliefentries=4 via.polygonreliefangle="90 Angle" via.airgapwidth=10
PolygonConnect copperRegion_SIG [(InNet('GND')) And OnLayer('SIG')] p11: connectstyle=Relief reliefconductorwidth=10 reliefentries=4 polygonreliefangle="90 Angle" airgapwidth=10 smdpad.connectstyle=Relief smdpad.reliefconductorwidth=10 smdpad.reliefentries=4 smdpad.polygonreliefangle="90 Angle" smdpad.airgapwidth=10 via.connectstyle=Relief via.reliefconductorwidth=10 via.reliefentries=4 via.polygonreliefangle="90 Angle" via.airgapwidth=10
PolygonConnect copperRegion [(InNet('GND'))] p12: connectstyle=Direct reliefconductorwidth=10 reliefentries=4 polygonreliefangle="90 Angle" airgapwidth=10 via.connectstyle=Relief via.reliefconductorwidth=10 via.reliefentries=4 via.polygonreliefangle="90 Angle" via.airgapwidth=10
RoutingVias viaSize [All] p1: holewidth=7.87 width=17.72 viastyle="Through Hole" minholewidth=7.87 minwidth=15.75 maxholewidth=248.03 maxwidth=393.7
SolderMaskExpansion solderMaskExpansion [IsVia] p1: expansion=-1000 istentingtop=TRUE
SolderMaskExpansion solderMaskExpansion [All] p2: expansion=2 istentingtop=FALSE
Width copperThickness2oz_2 [All] p1 off: maxlimit=10 minlimit=10 preferedwidth=10 toplayer_minwidth=8 toplayer_maxwidth=100 toplayer_prefwidth=10 bottomlayer_minwidth=8 bottomlayer_maxwidth=100 bottomlayer_prefwidth=10
Width copperThickness1oz_2 [All] p2: maxlimit=10 minlimit=10 preferedwidth=10 toplayer_minwidth=3.5 toplayer_maxwidth=100 toplayer_prefwidth=5 midlayer1_minwidth=3.5 midlayer1_maxwidth=100 midlayer1_prefwidth=5 midlayer2_minwidth=3.5 midlayer2_maxwidth=100 midlayer2_prefwidth=5 midlayer3_minwidth=3.5 midlayer3_maxwidth=100 midlayer3_prefwidth=5 midlayer4_minwidth=3.5 midlayer4_maxwidth=100 midlayer4_prefwidth=5 bottomlayer_minwidth=3.5 bottomlayer_maxwidth=100 bottomlayer_prefwidth=5

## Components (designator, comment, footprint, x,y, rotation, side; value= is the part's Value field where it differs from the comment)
AUDIO1 "PJ-327C-4A" AUDIO-SMD_PJ-327C-4A 3520,2986.46 r0 top
C1 "4.7uF" C0603 565,1151.46 r0 top
C2 "4.7uF" C0603 630,956.46 r90 top
C3 "4.7uF" C0603 695,956.46 r90 top
C4 "10uF" C0603 760,1256.46 r180 bottom
C5 "10uF" C0603 980,1256.46 r0 bottom
C6 "10uF" C0603 790,796.46 r0 top
C7 "10uF" C0603 955,1186.46 r270 bottom
C8 "10uF" C0603 1075,796.46 r180 top
C9 "10uF" C0603 845,1186.46 r270 bottom
C10 "10uF" C0603 530,1751.46 r270 top
C11 "1nF" C0603 1150,1101.46 r180 top
C12 "10uF" C0603 760,1361.46 r180 bottom
C13 "10uF" C0603 1145,1316.46 r180 top
C14 "10uF" C0603 1145,1381.46 r180 top
C15 "10uF" C0603 425,1616.46 r0 top
C16 "4.7uF" C0603 1585,1386.46 r270 top
C17 "10uF" C0603 940,1556.46 r270 top
C18 "10uF" C0603 1140,1461.46 r180 top
C19 "10uF" C0603 955,1411.46 r90 bottom
C20 "10uF" C0603 875,1556.46 r270 top
C21 "10uF" C0603 265,1276.46 r0 top
C22 "100nF" C0402 2245,2001.46 r90 top
C23 "100nF" C0402 2215,2001.46 r90 top
C24 "100nF" C0603 1050,681.46 r0 top
C25 "1uF" C0603 1005,1556.46 r90 top
C26 "1uF" C0402 2055,1726.46 r90 bottom
C27 "10uF" C0603 900,1411.46 r90 bottom
C28 "10uF" C0603 800,1186.46 r270 bottom
C29 "10uF" C0603 1145,1251.46 r180 top
C30 "10uF" C0603 1775,1966.46 r315 top
C31 "1uF" C0402 2350,1566.46 r180 bottom
C32 "1uF" C0402 2165.15,1687.35 r0 bottom
C33 "100nF" C0402 2215,1826.46 r270 bottom
C34 "1uF" C0402 1965,1876.46 r270 bottom
C35 "1uF" C0402 1959.73,1756.46 r90 bottom
C36 "100nF" C0402 1980,1531.46 r0 bottom
C37 "100nF" C0402 2080,1776.46 r180 bottom
C38 "100nF" C0402 2255,1686.46 r180 bottom
C39 "100nF" C0402 2365,1806.46 r180 bottom
C40 "100nF" C0402 1945,1801.46 r0 bottom
C41 "100nF" C0402 2420,1926.46 r270 bottom
C42 "100nF" C0402 1885.02,1802.36 r0 bottom
C43 "100nF" C0402 2100,1746.46 r0 bottom
C44 "100nF" C0402 2375,1596.46 r180 bottom
C45 "100nF" C0402 2235,1766.46 r270 bottom
C46 "100nF" C0402 2210,1701.46 r90 bottom
C47 "1nF" C0402 1930,1951.46 r270 bottom
C48 "4.7uF" C0603 2390,1661.46 r180 bottom
C49 "1uF" C0402 2350,1756.46 r90 bottom
C50 "100nF" C0402 2365,1696.46 r180 bottom
C51 "100nF" C0402 2515,1451.46 r180 top
C52 "100nF" C0402 2375,1626.46 r180 bottom
C53 "4.7uF" C0603 1900,1866.46 r0 bottom
C54 "10uF" C0603 1997.19,1773.71 r90 bottom
C55 "100nF" C0402 2045,1806.46 r180 bottom
C56 "1uF" C0402 2045,1836.46 r180 bottom
C57 "1nF" C0402 2800,1981.46 r180 top
C58 "100nF" C0402 2310,1741.46 r270 bottom
C59 "100nF" C0402 2327.81,1856.37 r0 bottom
C60 "22uF" C0603 2225,1641.46 r0 bottom
C61 "10uF" C0603 2225,1591.46 r0 bottom
C62 "1uF" C0402 2300,1676.46 r270 bottom
C63 "4.7uF" C0603 1810,2001.46 r315 top
C64 "100nF" C0402 2391.34,1926.46 r270 bottom
C65 "220nF" C0402 2440,1821.46 r180 bottom
C66 "100nF" C0402 1915,1906.46 r0 bottom
C67 "100nF" C0402 1975,1706.46 r0 bottom
C68 "1uF" C0402 2315,1631.46 r180 bottom
C69 "100nF" C0402 2295,1556.46 r90 bottom
C70 "100nF" C0402 2315,1601.46 r180 bottom
C71 "10uF" C0603 2025,1641.46 r0 bottom
C72 "10uF" C0603 2130,1641.46 r180 bottom
C73 "1uF" C0402 2040,1601.46 r0 bottom
C74 "1uF" C0402 2040,1571.46 r0 bottom
C75 "100nF" C0402 2110,1601.46 r180 bottom
C76 "100nF" C0402 2110,1571.46 r180 bottom
C77 "10uF" C0603 2270,1781.46 r270 bottom
C78 "1uF" C0402 2165,1716.46 r0 bottom
C79 "1uF" C0402 2255,1716.46 r180 bottom
C80 "100nF" C0402 2205,1766.46 r270 bottom
C81 "100nF" C0402 2320,1801.46 r90 bottom
C82 "10uF" C0603 2170,1781.46 r270 bottom
C83 "1nF" C0402 2400,1761.46 r270 bottom
C84 "1nF" C0402 2618.27,1538.47 r180 top
C85 "1uF" C0402 2805.98,1705.39 r0 top
C86 "22pF" C0402 2638.47,1828.46 r0 top
C87 "22pF" C0402 2560,2006.46 r0 top
C88 "22pF" C0402 2621.92,1661.69 r0 top
C89 "22pF" C0402 2544.6,1796.66 r0 top
C90 "100nF" C0402 2100,1716.46 r0 bottom
C91 "100nF" C0402 1810,1516.46 r0 top
C92 "100nF" C0402 2075,941.46 r0 top
C93 "10uF" C0603 2185,1026.46 r270 top
C94 "1uF" C0402 2405,736.46 r180 bottom
C95 "1uF" C0402 2260,686.46 r0 bottom
C96 "100nF" C0402 2405,781.46 r180 bottom
C97 "100nF" C0402 2405,821.46 r180 bottom
C98 "10uF" C0603 2005,651.46 r0 bottom
C99 "100nF" C0402 1735,901.46 r0 bottom
C100 "100nF" C0402 2040,616.46 r180 bottom
C101 "100nF" C0402 2295,616.46 r180 bottom
C102 "100nF" C0402 1735,861.46 r0 bottom
C103 "100nF" C0402 1935,691.46 r45 bottom
C104 "100nF" C0402 2425,671.46 r180 top
C105 "NC-100nF" C0402 2255,446.46 r180 top
C106 "NC-1uF" C0402 2255,401.46 r180 top
C107 "NC-10uF" C0603 2010,436.46 r0 top
C108 "100nF" C0402 2350,1531.46 r180 bottom
C109 "100nF" C0402 2425,631.46 r180 top
C110 "1uF" C0402 1735,771.46 r0 bottom
C111 "100nF" C0402 1810,1556.46 r0 top
C112 "NC-100nF" C0402 1890,431.46 r270 top
C113 "NC-100nF" C0402 1755,731.46 r0 bottom
C114 "100nF" C0402 2135,1026.46 r270 top
C115 "NC-100nF" C0402 2010,381.46 r0 top
C116 "NC-1uF" C0402 2150,1491.46 r270 bottom
C117 "10uF" C0603 2100,1496.46 r270 bottom
C118 "1uF" C0402 2040,1496.46 r0 bottom
C119 "1uF" C0402 2185,1516.46 r270 bottom
C120 "100nF" C0402 2270,1506.46 r180 bottom
C121 "100nF" C0402 2220,1516.46 r270 bottom
C122 "10uF" C0603 1855,666.46 r0 top
C123 "10uF" C0603 400,2746.46 r90 bottom
C124 "1uF" C0402 2330,2446.46 r180 top
C125 "10uF" C0603 2245,2701.46 r180 top
C126 "100nF" C0402 2245,2646.46 r0 top
C127 "1uF" C0402 1834.75,3252.8 r180 bottom
C128 "10uF" C0603 1785,3041.46 r180 bottom
C129 "100nF" C0402 1795,2986.46 r0 bottom
C130 "22uF" C0603 400,2406.46 r90 bottom
C131 "22uF" C0603 145,2086.46 r0 bottom
C132 "100nF" C0603 365,1856.46 r270 top
C133 "100nF" C0603 790,276.46 r270 top
C134 "39pF" C0603 1050,466.46 r180 top
C135 "22uF" C0603 1050,541.46 r0 top
C136 "22uF" C0603 1050,611.46 r0 top
C137 "100nF" C0603 1080,2396.46 r90 bottom
C138 "100nF" C0603 830,2396.46 r90 bottom
C139 "100nF" C0402 3160,2626.46 r270 top
C140 "100nF" C0402 3205,2736.46 r90 top
C141 "22uF" C0603 675,361.46 r0 top
C142 "470nF" C0603 3090,1536.46 r0 top
C143 "470nF" C0603 3065,1741.46 r0 top
C144 "470nF" C0603 1405,1606.46 r0 top
C145 "4.7uF" C0402 3770,2541.46 r270 top
C146 "4.7uF" C0402 3675,2541.46 r270 top
C147 "22uF" C0603 1145,1316.46 r180 bottom
C148 "22uF" C0603 650,296.46 r0 top
C149 "22uF" C0603 150,2021.46 r180 bottom
CN1 "KH-HDMI-19P-Cu" HDMI-SMD_KH-HDMI-19P-CU 2880,3016.46 r180 top
D1 "AZ1045-04F.R7G" DFN2510-10_L2.5-W1.0-P0.50-BL 1775,2541.46 r0 top
D2 "AZ1045-04F.R7G" DFN2510-10_L2.5-W1.0-P0.50-BL 2760,2751.46 r0 top
D3 "AZ1045-04F.R7G" DFN2510-10_L2.5-W1.0-P0.50-BL 2875,2751.46 r0 top
D4 "1N5819WS" SOD-323_L1.8-W1.3-LS2.5-RD 3035,2376.46 r270 top
D5 "1N5819WS" SOD-323_L1.8-W1.3-LS2.5-RD 3220,2626.46 r90 top
D6 "AZ1045-04F.R7G" DFN2510-10_L2.5-W1.0-P0.50-BL 3000,2756.46 r0 top
DC1 "DC-005-A200" DC-IN-TH_DC-005-A200 415,401.46 r0 top
H1 "PZ254V-11-03P" HDR-TH_3P-P2.54-V-M_PZ254V-11-03P 3625,1316.46 r90 top
H2 "PZ254V-11-02P" HDR-TH_2P-P2.54-V-M 85,1361.46 r270 top
J1 "HR911105A" RJ45-TH_HR911105A 1055,2836.46 r180 top
L1 "1.5uH" IND-SMD_L4.4-W4.2 520,1271.46 r180 top
L6 "6.8uH" IND-SMD_L7.0-W6.6 995,196.46 r0 top
L7 "1.5uH" IND-SMD_L4.4-W4.2 1025,961.46 r270 top
L8 "1.5uH" IND-SMD_L4.4-W4.2 845,961.46 r270 top
L9 "1.5uH" IND-SMD_L4.4-W4.2 705,1651.46 r180 top
L10 "1.5uH" IND-SMD_L4.4-W4.2 520,1476.46 r90 top
LED1 "GL0805UB01" LED0805-RD_BLUE 3255,1346.46 r180 top
LED2 "GL0805UB01" LED0805-RD_BLUE 3255,1431.46 r180 top
Q1 "BSN20" SOT-23-3_L2.9-W1.6-P1.90-LS2.8-BR 3235,2106.46 r270 top
Q2 "BSN20" SOT-23-3_L2.9-W1.6-P1.90-LS2.8-BR 3435,2106.46 r270 top
Q3 "BSN20" SOT-23-3_L2.9-W1.6-P1.90-LS2.8-BR 3150,2461.46 r270 top
Q4 "BSN20" SOT-23-3_L2.9-W1.6-P1.90-LS2.8-BR 3220,1206.46 r270 top
R1 "10kΩ" R0805 1995,2051.46 r90 bottom
R2 "2kΩ" R0805 1410,1116.46 r180 top
R3 "2kΩ" R0805 1410,1196.46 r180 top
R4 "0Ω" R0805 1410,1356.46 r180 top
R5 "0Ω" R0805 1410,1436.46 r180 top
R6 "0Ω" R0805 1410,1276.46 r0 top
R7 "10kΩ" R0805 2812.91,1767.18 r0 top
R8 "1kΩ" R0805 2785,1451.46 r180 top
R9 "2kΩ" R0805 2060,2051.46 r90 bottom
R10 "2kΩ" R0805 1930,2051.46 r90 bottom
R11 "10kΩ" R0805 2557.93,1599.99 r0 top
R12 "10kΩ" R0805 2640,1451.46 r180 top
R13 "100Ω" R0805 2145,436.46 r180 bottom
R14 "1kΩ" R0805 2812.76,1931.79 r0 top
R15 "100kΩ" R0805 720,511.46 r270 top
R16 "1MΩ" R0805 640,511.46 r90 top
R17 "240Ω" R0805 1775,1451.46 r0 top
R18 "240Ω" R0805 1845,516.46 r180 top
R19 "0Ω" R0805 3285,2626.46 r90 top
R21 "2kΩ" R0402 2110,981.46 r0 top
R22 "2kΩ" R0402 2155,941.46 r0 top
R23 "33Ω" R0805 1364.91,2151.58 r180 bottom
R24 "6.8kΩ" R0805 2160,2691.46 r270 top
R25 "10KΩ" R0805 161.03,2677.86 r90 bottom
R26 "10KΩ" R0805 241.48,2676.56 r90 bottom
R27 "10KΩ" R0805 325.1,2676.56 r90 bottom
R28 "10KΩ" R0805 470.16,2676.5 r90 bottom
R29 "10KΩ" R0805 549.18,2676.53 r90 bottom
R30 "240Ω" R0805 1845,596.46 r180 top
R31 "100kΩ" R0805 2159.37,2535.83 r270 top
R32 "NC-0Ω" R0805 2320,2536.46 r90 bottom
R33 "1.8kΩ" R0805 3195,2226.46 r180 top
R34 "100kΩ" R0805 1693.3,3281.46 r0 bottom
R35 "NC-0Ω" R0805 1895,3156.46 r270 bottom
R36 "1.8kΩ" R0805 3395,2226.46 r180 top
R37 "5.1kΩ" R0805 415,2101.46 r180 bottom
R38 "5.1kΩ" R0805 415,2036.46 r180 bottom
R39 "0Ω" R0805 420,1896.46 r0 bottom
R40 "0Ω" R0805 420,1956.46 r0 bottom
R41 "0Ω" R0805 1190,926.46 r0 bottom
R42 "0Ω" R0805 1190,1006.46 r0 bottom
R43 "110kΩ" R0805 1065,386.46 r0 top
R44 "15kΩ" R0805 945,576.46 r270 top
R45 "1kΩ" R0805 1337.04,2390.54 r90 bottom
R46 "1kΩ" R0805 770,2381.46 r90 bottom
R47 "1kΩ" R0805 3140,2736.46 r90 top
R48 "0Ω" R0805 3045,1991.46 r0 top
R49 "10KΩ" R0805 3230,1986.46 r0 top
R50 "330Ω" R0805 3060,1346.46 r0 top
R51 "330Ω" R0805 3060,1426.46 r0 top
R52 "10KΩ" R0805 3440,1986.46 r0 top
R53 "56kΩ" R0805 3160,2346.46 r180 top
R54 "56kΩ" R0805 3040,2526.46 r270 top
R55 "6.8kΩ" R0805 1630,3096.46 r0 bottom
R56 "10kΩ" R0805 1160,1176.46 r180 top
R57 "10KΩ" R0805 627.65,2677.15 r90 bottom
R58 "1kΩ" R0805 3085,1636.46 r0 top
R59 "1kΩ" R0805 3055.88,1825.66 r0 top
R60 "1kΩ" R0805 1415,1531.46 r0 top
R61 "0Ω" R0805 3410,1191.46 r0 top
R62 "10KΩ" R0805 3060,1256.46 r0 top
R63 "0Ω" R0805 3780,2666.46 r90 top
R64 "0Ω" R0805 3670,2666.46 r90 top
R65 "3kΩ" R0805 1800,2051.46 r270 bottom
R66 "3kΩ" R0805 1865,2051.46 r270 bottom
R67 "150kΩ" R0805 2814.66,1847.21 r0 top
R68 "2kΩ" R0402 1930,431.46 r90 top
R69 "2kΩ" R0402 1910,376.46 r0 top
SW1 "TS-KG89S-AT25F" SW-SMD_4P-L4.2-W3.3-P2.15-LS5.1 3310,1566.46 r0 top
SW2 "TS-KG89S-AT25F" SW-SMD_4P-L4.2-W3.3-P2.15-LS5.1 3310,1791.46 r0 top
SW3 "TS-KG89S-AT25F" SW-SMD_4P-L4.2-W3.3-P2.15-LS5.1 1165,1951.46 r180 top
U1 "AXP805" QFN-56_L7.0-W7.0-P0.40-TL-EP5.2 869.02,1299.33 r90 top
U2 "H6-BGA-1219" H6_BGA451 2165,1626.46 r270 top
U3 "HX TF PUSH" TF-SMD_TF-PUSH 360,2721.46 r180 top
U4 "SY6280AAC" SOT-23-5_L3.0-W1.7-P0.95-LS2.8-BL 2270,2536.46 r180 top
U6 "RT7295AGJ6F" SOT-23-6_L2.9-W1.6-P0.95-LS2.8-BR 875,421.46 r0 top
U7 "SY6280AAC" SOT-23-5_L3.0-W1.7-P0.95-LS2.8-BL 1780,3156.46 r180 bottom
UD2 "LPDDR3_FBGA178" LPDDR3_FBGA178 2150,696.46 r90 top
USB2 "906-162A1011D10200" USB-A-TH_4P-P1.40-V-F-C39416 2320,2996.46 r180 top
USB3 "USB-303WSD-BRY" USB-A-TH_XUNPU_USB-303WSD-BRY 1760,2826.46 r180 top
USB4 "TYPE-C 16PIN 2MD(073)" USB-C-SMD_TYPE-C-16PIN-2MD-073 200,2071.46 r270 top
X1 "24MHz" CRYSTAL-SMD_4P-L3.2-W2.5-BL 2592,1917.53 r180 top
X2 "32.768kHz" OSC-SMD_L3.2-W1.5 2590.75,1727.05 r0 top

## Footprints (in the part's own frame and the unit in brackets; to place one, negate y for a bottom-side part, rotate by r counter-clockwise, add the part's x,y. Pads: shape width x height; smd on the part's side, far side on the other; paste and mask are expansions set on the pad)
AUDIO-SMD_PJ-327C-4A [mm]
  rect 2.8x1.8 smd: 1(-3.4,4.275) 2(-3.4,-2.625)
  rect 2.5x1.8 smd: 3(3.4,1.525)
  rect 3x1.8 smd: 4(3.4,-4.275)
  Board Outline Layer circle w0.003: c0,3.825 r0.75
  Board Outline Layer circle w0.003: c0,-2.175 r0.75
  Board Outline Layer region: 0.75,3.825 0.676,3.5 0.468,3.239 0.167,3.094 -0.167,3.094 -0.468,3.239 -0.676,3.5 -0.75,3.825 -0.75,3.825 -0.676,4.151 -0.468,4.411 -0.167,4.556 0.167,4.556 0.468,4.411 0.676,4.151 0.75,3.825
  Board Outline Layer region: 0.75,3.825 0.741,3.708 0.713,3.593 0.668,3.485 0.607,3.384 0.53,3.295 0.441,3.218 0.34,3.157 0.232,3.112 0.117,3.084 0,3.075 -0.117,3.084 -0.232,3.112 -0.34,3.157 -0.441,3.218 -0.53,3.295 -0.607,3.384 -0.668,3.485 -0.713,3.593 -0.741,3.708 -0.75,3.825 -0.741,3.942 -0.713,4.057 -0.668,4.166 -0.607,4.266 -0.53,4.355 -0.441,4.432 -0.34,4.493 -0.232,4.538 -0.117,4.566 0,4.575 0.117,4.566 0.232,4.538 0.34,4.493 0.441,4.432 0.53,4.355 0.607,4.266 0.668,4.166 0.713,4.057 0.741,3.942
  Board Outline Layer region: 0.75,-2.175 0.676,-2.501 0.468,-2.762 0.167,-2.906 -0.167,-2.906 -0.468,-2.762 -0.676,-2.501 -0.75,-2.175 -0.75,-2.175 -0.676,-1.85 -0.468,-1.589 -0.167,-1.444 0.167,-1.444 0.468,-1.589 0.676,-1.85 0.75,-2.175
  Board Outline Layer region: 0.75,-2.175 0.741,-2.292 0.713,-2.407 0.668,-2.516 0.607,-2.616 0.53,-2.705 0.441,-2.782 0.34,-2.843 0.232,-2.888 0.117,-2.916 0,-2.925 -0.117,-2.916 -0.232,-2.888 -0.34,-2.843 -0.441,-2.782 -0.53,-2.705 -0.607,-2.616 -0.668,-2.516 -0.713,-2.407 -0.741,-2.292 -0.75,-2.175 -0.741,-2.058 -0.713,-1.943 -0.668,-1.835 -0.607,-1.734 -0.53,-1.645 -0.441,-1.568 -0.34,-1.507 -0.232,-1.462 -0.117,-1.434 0,-1.425 0.117,-1.434 0.232,-1.462 0.34,-1.507 0.441,-1.568 0.53,-1.645 0.607,-1.734 0.668,-1.835 0.713,-1.943 0.741,-2.058
  Multi-Layer board cut-out: 0.75,3.825 0.676,3.5 0.468,3.239 0.167,3.094 -0.167,3.094 -0.468,3.239 -0.676,3.5 -0.75,3.825 -0.75,3.825 -0.676,4.151 -0.468,4.411 -0.167,4.556 0.167,4.556 0.468,4.411 0.676,4.151 0.75,3.825
  Multi-Layer board cut-out: 0.75,-2.175 0.676,-2.501 0.468,-2.762 0.167,-2.906 -0.167,-2.906 -0.468,-2.762 -0.676,-2.501 -0.75,-2.175 -0.75,-2.175 -0.676,-1.85 -0.468,-1.589 -0.167,-1.444 0.167,-1.444 0.468,-1.589 0.676,-1.85 0.75,-2.175
  silkscreen extent -3.2,-5.67 3.2,8.91
C0402 [mm]
  rect 0.5x0.54 smd: 1(-0.42,0) 2(0.42,0)
  silkscreen extent -0.87,-0.5 0.87,0.5
C0603 [mm]
  rect 0.8x0.9 smd: 1(-0.7,0) 2(0.7,0)
  silkscreen extent -1.39,-0.71 1.39,0.71
CRYSTAL-SMD_4P-L3.2-W2.5-BL [mm]
  rect 1.4x1.2 smd: 1(-1.1,-0.85) 2(1.1,-0.85) 3(1.1,0.85) 4(-1.1,0.85)
  silkscreen extent -2.26,-1.91 2.03,1.68
DC-IN-TH_DC-005-A200 [mm]
  oval 1.5x3.8 hole 0.9 slot 3.1 at 90 deg copper offset -0.001,0: 1(3.001,2.325)
  oval 1.5x3.8 hole 0.9 slot 3.1 at 90 deg copper offset 0,0: 2(-3,2.325)
  oval 3.4x1.5 hole 0.9 slot 2.6 at 0 deg copper offset 0,-0.001: 3(0.5,-2.325)
  silkscreen extent -10.5,-2.17 3.5,6.83
DFN2510-10_L2.5-W1.0-P0.50-BL [mm]
  rect 0.2x0.665 smd paste-100 mask+0.051: 1(-1,-0.433) 2(-0.5,-0.433) 4(0.5,-0.433) 5(1,-0.433) 6(1,0.433) 7(0.5,0.433) 9(-0.5,0.433) 10(-1,0.433)
  rect 0.4x0.665 smd paste-100 mask+0.051: 3(0,-0.433) 8(0,0.433)
  silkscreen extent -1.33,-1.11 1.33,0.58
H6_BGA451 [mm]
  round 0.3 smd paste+0 mask+0: A1(-7.15,-7.15) A3(-7.15,-5.85) A5(-7.15,-4.55) A6(-7.15,-3.9) A8(-7.15,-2.6) A9(-7.15,-1.95) A10(-7.15,-1.3) A12(-7.15,0) A13(-7.15,0.65) A14(-7.15,1.3) A16(-7.15,2.6) A17(-7.15,3.25) A18(-7.15,3.9) A19(-7.15,4.55) A20(-7.15,5.2) A21(-7.15,5.85) A22(-7.15,6.5) A23(-7.15,7.15) AA1(5.85,-7.15) AA2(5.85,-6.5) AA3(5.85,-5.85) AA4(5.85,-5.2) AA5(5.85,-4.55) AA7(5.85,-3.25) AA8(5.85,-2.6) AA10(5.85,-1.3) AA11(5.85,-0.65) AA13(5.85,0.65) AA14(5.85,1.3) AA15(5.85,1.95) AA16(5.85,2.6) AA17(5.85,3.25) AA19(5.85,4.55) AA20(5.85,5.2) AA21(5.85,5.85) AA22(5.85,6.5) AA23(5.85,7.15) AB1(6.5,-7.15) AB2(6.5,-6.5) AB3(6.5,-5.85) AB4(6.5,-5.2) AB5(6.5,-4.55) AB6(6.5,-3.9) AB7(6.5,-3.25) AB8(6.5,-2.6) AB9(6.5,-1.95) AB10(6.5,-1.3) AB11(6.5,-0.65) AB12(6.5,0) AB13(6.5,0.65) AB14(6.5,1.3) AB15(6.5,1.95) AB16(6.5,2.6) AB17(6.5,3.25) AB18(6.5,3.9) AB19(6.5,4.55) AB20(6.5,5.2) AB21(6.5,5.85) AB22(6.5,6.5) AB23(6.5,7.15) AC1(7.15,-7.15) AC2(7.15,-6.5) AC3(7.15,-5.85) AC4(7.15,-5.2) AC5(7.15,-4.55) AC6(7.15,-3.9) AC7(7.15,-3.25) AC8(7.15,-2.6) AC9(7.15,-1.95) AC10(7.15,-1.3) AC11(7.15,-0.65) AC12(7.15,0) AC13(7.15,0.65) AC14(7.15,1.3) AC15(7.15,1.95) AC16(7.15,2.6) AC17(7.15,3.25) AC18(7.15,3.9) AC19(7.15,4.55) AC20(7.15,5.2) AC21(7.15,5.85) AC22(7.15,6.5) AC23(7.15,7.15) B1(-6.5,-7.15) B2(-6.5,-6.5) B3(-6.5,-5.85) B4(-6.5,-5.2) B5(-6.5,-4.55) B6(-6.5,-3.9) B7(-6.5,-3.25) B8(-6.5,-2.6) B9(-6.5,-1.95) B10(-6.5,-1.3) B12(-6.5,0) B13(-6.5,0.65) B14(-6.5,1.3) B15(-6.5,1.95) B16(-6.5,2.6) B17(-6.5,3.25) B18(-6.5,3.9) B19(-6.5,4.55) B20(-6.5,5.2) B21(-6.5,5.85) B22(-6.5,6.5) B23(-6.5,7.15) C1(-5.85,-7.15) C2(-5.85,-6.5) C3(-5.85,-5.85) C4(-5.85,-5.2) C5(-5.85,-4.55) C7(-5.85,-3.25) C8(-5.85,-2.6) C9(-5.85,-1.95) C12(-5.85,0) C13(-5.85,0.65) C14(-5.85,1.3) C15(-5.85,1.95) C16(-5.85,2.6) C18(-5.85,3.9) C19(-5.85,4.55) C20(-5.85,5.2) C22(-5.85,6.5) C23(-5.85,7.15) D1(-5.2,-7.15) D2(-5.2,-6.5) D3(-5.2,-5.85) D4(-5.2,-5.2) D5(-5.2,-4.55) D9(-5.2,-1.95) D11(-5.2,-0.65) D12(-5.2,0) D15(-5.2,1.95) D16(-5.2,2.6) D18(-5.2,3.9) D19(-5.2,4.55) D20(-5.2,5.2) D21(-5.2,5.85) D22(-5.2,6.5) D23(-5.2,7.15) E1(-4.55,-7.15) E2(-4.55,-6.5) E3(-4.55,-5.85) E4(-4.55,-5.2) E5(-4.55,-4.55) E6(-4.55,-3.9) E7(-4.55,-3.25) E8(-4.55,-2.6) E9(-4.55,-1.95) E10(-4.55,-1.3) E11(-4.55,-0.65) E12(-4.55,0) E13(-4.55,0.65) E14(-4.55,1.3) E15(-4.55,1.95) E16(-4.55,2.6) E17(-4.55,3.25) E18(-4.55,3.9) E19(-4.55,4.55) E21(-4.55,5.85) E22(-4.55,6.5) F1(-3.9,-7.15) F2(-3.9,-6.5) F3(-3.9,-5.85) F5(-3.9,-4.55) F7(-3.9,-3.25) F8(-3.9,-2.6) F9(-3.9,-1.95) F11(-3.9,-0.65) F12(-3.9,0) F13(-3.9,0.65) F14(-3.9,1.3) F15(-3.9,1.95) F16(-3.9,2.6) F17(-3.9,3.25) F19(-3.9,4.55) F20(-3.9,5.2) F21(-3.9,5.85) F22(-3.9,6.5) F23(-3.9,7.15) G2(-3.25,-6.5) G3(-3.25,-5.85) G7(-3.25,-3.25) G8(-3.25,-2.6) G9(-3.25,-1.95) G10(-3.25,-1.3) G11(-3.25,-0.65) G12(-3.25,0) G13(-3.25,0.65) G14(-3.25,1.3) G15(-3.25,1.95) G16(-3.25,2.6) G17(-3.25,3.25) G20(-3.25,5.2) G21(-3.25,5.85) G22(-3.25,6.5) H1(-2.6,-7.15) H2(-2.6,-6.5) H3(-2.6,-5.85) H4(-2.6,-5.2) H5(-2.6,-4.55) H6(-2.6,-3.9) H7(-2.6,-3.25) H8(-2.6,-2.6) H9(-2.6,-1.95) H10(-2.6,-1.3) H11(-2.6,-0.65) H12(-2.6,0) H13(-2.6,0.65) H14(-2.6,1.3) H15(-2.6,1.95) H16(-2.6,2.6) H17(-2.6,3.25) H18(-2.6,3.9) H19(-2.6,4.55) H20(-2.6,5.2) H21(-2.6,5.85) H22(-2.6,6.5) H23(-2.6,7.15) J2(-1.95,-6.5) J3(-1.95,-5.85) J5(-1.95,-4.55) J6(-1.95,-3.9) J7(-1.95,-3.25) J8(-1.95,-2.6) J9(-1.95,-1.95) J10(-1.95,-1.3) J11(-1.95,-0.65) J12(-1.95,0) J13(-1.95,0.65) J14(-1.95,1.3) J15(-1.95,1.95) J16(-1.95,2.6) J17(-1.95,3.25) J19(-1.95,4.55) J20(-1.95,5.2) J21(-1.95,5.85) J22(-1.95,6.5) K1(-1.3,-7.15) K2(-1.3,-6.5) K3(-1.3,-5.85) K7(-1.3,-3.25) K8(-1.3,-2.6) K9(-1.3,-1.95) K10(-1.3,-1.3) K11(-1.3,-0.65) K12(-1.3,0) K13(-1.3,0.65) K14(-1.3,1.3) K15(-1.3,1.95) K16(-1.3,2.6) K17(-1.3,3.25) K18(-1.3,3.9) K20(-1.3,5.2) K21(-1.3,5.85) K22(-1.3,6.5) K23(-1.3,7.15) L2(-0.65,-6.5) L3(-0.65,-5.85) L4(-0.65,-5.2) L5(-0.65,-4.55) L6(-0.65,-3.9) L7(-0.65,-3.25) L8(-0.65,-2.6) L9(-0.65,-1.95) L10(-0.65,-1.3) L11(-0.65,-0.65) L12(-0.65,0) L13(-0.65,0.65) L14(-0.65,1.3) L15(-0.65,1.95) L16(-0.65,2.6) L17(-0.65,3.25) L18(-0.65,3.9) L19(-0.65,4.55) L20(-0.65,5.2) L21(-0.65,5.85) L22(-0.65,6.5) M1(0,-7.15) M2(0,-6.5) M3(0,-5.85) M4(0,-5.2) M5(0,-4.55) M6(0,-3.9) M7(0,-3.25) M8(0,-2.6) M9(0,-1.95) M10(0,-1.3) M11(0,-0.65) M12(0,0) M13(0,0.65) M14(0,1.3) M15(0,1.95) M16(0,2.6) M17(0,3.25) M18(0,3.9) M19(0,4.55) M21(0,5.85) M22(0,6.5) M23(0,7.15) N2(0.65,-6.5) N3(0.65,-5.85) N7(0.65,-3.25) N8(0.65,-2.6) N9(0.65,-1.95) N10(0.65,-1.3) N11(0.65,-0.65) N12(0.65,0) N13(0.65,0.65) N14(0.65,1.3) N15(0.65,1.95) N16(0.65,2.6) N17(0.65,3.25) N18(0.65,3.9) N19(0.65,4.55) N20(0.65,5.2) N22(0.65,6.5) N23(0.65,7.15) P1(1.3,-7.15) P2(1.3,-6.5) P3(1.3,-5.85) P4(1.3,-5.2) P5(1.3,-4.55) P6(1.3,-3.9) P7(1.3,-3.25) P8(1.3,-2.6) P9(1.3,-1.95) P10(1.3,-1.3) P11(1.3,-0.65) P12(1.3,0) P13(1.3,0.65) P14(1.3,1.3) P15(1.3,1.95) P16(1.3,2.6) P17(1.3,3.25) P18(1.3,3.9) P19(1.3,4.55) P20(1.3,5.2) P21(1.3,5.85) P22(1.3,6.5) R2(1.95,-6.5) R3(1.95,-5.85) R5(1.95,-4.55) R6(1.95,-3.9) R7(1.95,-3.25) R8(1.95,-2.6) R9(1.95,-1.95) R10(1.95,-1.3) R11(1.95,-0.65) R12(1.95,0) R13(1.95,0.65) R14(1.95,1.3) R15(1.95,1.95) R16(1.95,2.6) R17(1.95,3.25) R18(1.95,3.9) R19(1.95,4.55) R20(1.95,5.2) R21(1.95,5.85) R22(1.95,6.5) R23(1.95,7.15) T1(2.6,-7.15) T2(2.6,-6.5) T3(2.6,-5.85) T7(2.6,-3.25) T8(2.6,-2.6) T9(2.6,-1.95) T10(2.6,-1.3) T11(2.6,-0.65) T12(2.6,0) T13(2.6,0.65) T14(2.6,1.3) T15(2.6,1.95) T16(2.6,2.6) T17(2.6,3.25) T18(2.6,3.9) T19(2.6,4.55) T20(2.6,5.2) T21(2.6,5.85) T22(2.6,6.5) U2(3.25,-6.5) U3(3.25,-5.85) U4(3.25,-5.2) U5(3.25,-4.55) U6(3.25,-3.9) U7(3.25,-3.25) U8(3.25,-2.6) U9(3.25,-1.95) U10(3.25,-1.3) U11(3.25,-0.65) U12(3.25,0) U13(3.25,0.65) U14(3.25,1.3) U15(3.25,1.95) U16(3.25,2.6) U17(3.25,3.25) U18(3.25,3.9) U19(3.25,4.55) U21(3.25,5.85) U22(3.25,6.5) U23(3.25,7.15) V1(3.9,-7.15) V2(3.9,-6.5) V3(3.9,-5.85) V5(3.9,-4.55) V6(3.9,-3.9) V7(3.9,-3.25) V9(3.9,-1.95) V10(3.9,-1.3) V11(3.9,-0.65) V13(3.9,0.65) V15(3.9,1.95) V17(3.9,3.25) V19(3.9,4.55) V20(3.9,5.2) V21(3.9,5.85) V22(3.9,6.5) V23(3.9,7.15) W1(4.55,-7.15) W2(4.55,-6.5) W3(4.55,-5.85) W4(4.55,-5.2) W5(4.55,-4.55) W7(4.55,-3.25) W8(4.55,-2.6) W10(4.55,-1.3) W11(4.55,-0.65) W13(4.55,0.65) W14(4.55,1.3) W16(4.55,2.6) W17(4.55,3.25) W19(4.55,4.55) W21(4.55,5.85) W22(4.55,6.5) W23(4.55,7.15) Y1(5.2,-7.15) Y2(5.2,-6.5) Y3(5.2,-5.85) Y5(5.2,-4.55) Y7(5.2,-3.25) Y8(5.2,-2.6) Y10(5.2,-1.3) Y11(5.2,-0.65) Y13(5.2,0.65) Y14(5.2,1.3) Y16(5.2,2.6) Y17(5.2,3.25) Y19(5.2,4.55) Y20(5.2,5.2) Y21(5.2,5.85) Y22(5.2,6.5) Y23(5.2,7.15)
  silkscreen extent -7.65,-7.65 7.65,7.65
HDMI-SMD_KH-HDMI-19P-CU [mm]
  rect 0.3x2.6 smd paste-100 mask+0.051: 1(4.5,3.36) 2(4,3.36) 3(3.5,3.36) 4(3,3.36) 5(2.5,3.36) 6(2,3.36) 7(1.5,3.36) 8(1,3.36) 9(0.5,3.36) 10(0,3.36) 11(-0.5,3.36) 12(-1,3.36) 13(-1.5,3.36) 14(-2,3.36) 15(-2.5,3.36) 16(-3,3.36) 17(-3.5,3.36) 18(-4,3.36) 19(-4.5,3.36)
  oval 2x3.5 hole 1 slot 2.8 at 90 deg: 20(-7.25,2.6) 21(7.25,2.6)
  oval 2x2.5 hole 1 slot 1.8 at 90 deg: 22(-7.25,-3.36) 23(7.25,-3.36)
  silkscreen extent -7.62,-8.13 7.62,4.57
HDR-TH_2P-P2.54-V-M [mm]
  rect 2x2 hole 1.2: 1(-1.27,0)
  round 2 hole 1.2: 2(1.27,0)
  silkscreen extent -2.54,-1.27 2.54,1.27
HDR-TH_3P-P2.54-V-M_PZ254V-11-03P [mm]
  rect 1.7x1.7 hole 1.02: 1(-2.54,0)
  round 1.7 hole 1.02: 2(0,0) 3(2.54,0)
  silkscreen extent -3.81,-1.25 3.81,1.25
IND-SMD_L4.4-W4.2 [mm]
  rect 1.4x2.12 smd: 1(2.028,0) 2(-2.028,0)
  silkscreen extent -2.28,-2.18 2.28,2.18
IND-SMD_L7.0-W6.6 [mm]
  rect 2.4x3.2 smd: 1(-3,0) 2(3,0)
  silkscreen extent -3.5,-3.3 3.5,3.3
LED0805-RD_BLUE [mm]
  rect 1x1.25 smd: 1(-1.1,0) 2(1.1,0)
  silkscreen extent -2.1,-0.95 1.98,0.96
LPDDR3_FBGA178 [mm]
  round 0.3 smd paste+0 mask+0: A1(-4.8,5.2) A2(-4,5.2) A3(-3.2,5.2) A4(-2.4,5.2) A5(-1.6,5.2) A6(-0.8,5.2) A8(0.8,5.2) A9(1.6,5.2) A10(2.4,5.2) A11(3.2,5.2) A12(4,5.2) A13(4.8,5.2) B1(-4.8,4.55) B2(-4,4.55) B3(-3.2,4.55) B4(-2.4,4.55) B5(-1.6,4.55) B6(-0.8,4.55) B8(0.8,4.55) B9(1.6,4.55) B10(2.4,4.55) B11(3.2,4.55) B12(4,4.55) B13(4.8,4.55) C2(-4,3.9) C3(-3.2,3.9) C4(-2.4,3.9) C5(-1.6,3.9) C6(-0.8,3.9) C8(0.8,3.9) C9(1.6,3.9) C10(2.4,3.9) C11(3.2,3.9) C12(4,3.9) D2(-4,3.25) D3(-3.2,3.25) D4(-2.4,3.25) D5(-1.6,3.25) D6(-0.8,3.25) D8(0.8,3.25) D9(1.6,3.25) D10(2.4,3.25) D11(3.2,3.25) D12(4,3.25) E2(-4,2.6) E3(-3.2,2.6) E4(-2.4,2.6) E5(-1.6,2.6) E6(-0.8,2.6) E8(0.8,2.6) E9(1.6,2.6) E10(2.4,2.6) E11(3.2,2.6) E12(4,2.6) F2(-4,1.95) F3(-3.2,1.95) F4(-2.4,1.95) F5(-1.6,1.95) F6(-0.8,1.95) F8(0.8,1.95) F9(1.6,1.95) F10(2.4,1.95) F11(3.2,1.95) F12(4,1.95) G2(-4,1.3) G3(-3.2,1.3) G4(-2.4,1.3) G5(-1.6,1.3) G6(-0.8,1.3) G8(0.8,1.3) G9(1.6,1.3) G10(2.4,1.3) G11(3.2,1.3) G12(4,1.3) H2(-4,0.65) H3(-3.2,0.65) H4(-2.4,0.65) H5(-1.6,0.65) H6(-0.8,0.65) H8(0.8,0.65) H9(1.6,0.65) H10(2.4,0.65) H11(3.2,0.65) H12(4,0.65) J2(-4,0) J3(-3.2,0) J4(-2.4,0) J5(-1.6,0) J6(-0.8,0) J8(0.8,0) J9(1.6,0) J10(2.4,0) J11(3.2,0) J12(4,0) K2(-4,-0.65) K3(-3.2,-0.65) K4(-2.4,-0.65) K5(-1.6,-0.65) K6(-0.8,-0.65) K8(0.8,-0.65) K9(1.6,-0.65) K10(2.4,-0.65) K11(3.2,-0.65) K12(4,-0.65) L2(-4,-1.3) L3(-3.2,-1.3) L4(-2.4,-1.3) L5(-1.6,-1.3) L6(-0.8,-1.3) L8(0.8,-1.3) L9(1.6,-1.3) L10(2.4,-1.3) L11(3.2,-1.3) L12(4,-1.3) M2(-4,-1.95) M3(-3.2,-1.95) M4(-2.4,-1.95) M5(-1.6,-1.95) M6(-0.8,-1.95) M8(0.8,-1.95) M9(1.6,-1.95) M10(2.4,-1.95) M11(3.2,-1.95) M12(4,-1.95) N2(-4,-2.6) N3(-3.2,-2.6) N4(-2.4,-2.6) N5(-1.6,-2.6) N6(-0.8,-2.6) N8(0.8,-2.6) N9(1.6,-2.6) N10(2.4,-2.6) N11(3.2,-2.6) N12(4,-2.6) P2(-4,-3.25) P3(-3.2,-3.25) P4(-2.4,-3.25) P5(-1.6,-3.25) P6(-0.8,-3.25) P8(0.8,-3.25) P9(1.6,-3.25) P10(2.4,-3.25) P11(3.2,-3.25) P12(4,-3.25) R2(-4,-3.9) R3(-3.2,-3.9) R4(-2.4,-3.9) R5(-1.6,-3.9) R6(-0.8,-3.9) R8(0.8,-3.9) R9(1.6,-3.9) R10(2.4,-3.9) R11(3.2,-3.9) R12(4,-3.9) T1(-4.8,-4.55) T2(-4,-4.55) T3(-3.2,-4.55) T4(-2.4,-4.55) T5(-1.6,-4.55) T6(-0.8,-4.55) T8(0.8,-4.55) T9(1.6,-4.55) T10(2.4,-4.55) T11(3.2,-4.55) T12(4,-4.55) T13(4.8,-4.55) U1(-4.8,-5.2) U2(-4,-5.2) U3(-3.2,-5.2) U4(-2.4,-5.2) U5(-1.6,-5.2) U6(-0.8,-5.2) U8(0.8,-5.2) U9(1.6,-5.2) U10(2.4,-5.2) U11(3.2,-5.2) U12(4,-5.2) U13(4.8,-5.2)
  silkscreen extent -5.58,-5.82 5.58,5.82
OSC-SMD_L3.2-W1.5 [mm]
  rect 0.85x1.7 smd: 1(-1.155,0) 2(1.155,0)
  silkscreen extent -2.03,-1.08 2.03,1.08
QFN-56_L7.0-W7.0-P0.40-TL-EP5.2 [mm]
  rect 0.7x0.2 smd paste-100 mask+0.05: 1(-3.45,2.6) 2(-3.45,2.2) 3(-3.45,1.8) 4(-3.45,1.4) 5(-3.45,1) 6(-3.45,0.6) 7(-3.45,0.2) 8(-3.45,-0.2) 9(-3.45,-0.6) 10(-3.45,-1) 11(-3.45,-1.4) 12(-3.45,-1.8) 13(-3.45,-2.2) 14(-3.45,-2.6) 29(3.45,-2.6) 30(3.45,-2.2) 31(3.45,-1.8) 32(3.45,-1.4) 33(3.45,-1) 34(3.45,-0.6) 35(3.45,-0.2) 36(3.45,0.2) 37(3.45,0.6) 38(3.45,1) 39(3.45,1.4) 40(3.45,1.8) 41(3.45,2.2) 42(3.45,2.6)
  rect 0.2x0.7 smd paste-100 mask+0.05: 15(-2.6,-3.45) 16(-2.2,-3.45) 17(-1.8,-3.45) 18(-1.4,-3.45) 19(-1,-3.45) 20(-0.6,-3.45) 21(-0.2,-3.45) 22(0.2,-3.45) 23(0.6,-3.45) 24(1,-3.45) 25(1.4,-3.45) 26(1.8,-3.45) 27(2.2,-3.45) 28(2.6,-3.45) 43(2.6,3.45) 44(2.2,3.45) 45(1.8,3.45) 46(1.4,3.45) 47(1,3.45) 48(0.6,3.45) 49(0.2,3.45) 50(-0.2,3.45) 51(-0.6,3.45) 52(-1,3.45) 53(-1.4,3.45) 54(-1.8,3.45) 55(-2.2,3.45) 56(-2.6,3.45)
  rect 5.2x5.2 smd paste-100 mask+0.05: 57(0,0)
  silkscreen extent -4.22,-3.5 3.5,3.5
R0402 [mm]
  rect 0.566x0.54 smd paste-100 mask+0.051: 1(-0.433,0) 2(0.433,0)
  silkscreen extent -0.94,-0.5 0.94,0.5
R0805 [mm]
  rect 1.133x1.377 smd paste-100 mask+0.051: 1(-1,0) 2(1,0)
  silkscreen extent -1.76,-0.92 1.76,0.92
RJ45-TH_HR911105A [mm]
  rect 1.6x1.6 hole 1: 1(-4.45,4.355)
  round 1.6 hole 1: 2(-3.18,6.895) 3(-1.91,4.355) 4(-0.64,6.895) 5(0.63,4.355) 6(1.9,6.895) 7(3.17,4.355) 8(4.44,6.895)
  round 1.8 hole 1.1: 9(-6.625,-6.895) 10(-4.085,-6.895) 11(4.085,-6.895) 12(6.625,-6.895)
  round 2.5 hole 1.8: SH1(-7.745,1.055) SH2(7.745,1.055)
  Board Outline Layer circle w0.003: c-5.715,-1.995 r1.65
  Board Outline Layer circle w0.003: c5.715,-1.995 r1.65
  Board Outline Layer region: -7.365,-1.995 -7.202,-1.279 -6.744,-0.705 -6.082,-0.386 -5.348,-0.386 -4.686,-0.705 -4.228,-1.279 -4.065,-1.995 -4.065,-1.995 -4.228,-2.711 -4.686,-3.285 -5.348,-3.604 -6.082,-3.604 -6.744,-3.285 -7.202,-2.711 -7.365,-1.995
  Board Outline Layer region: -7.365,-1.995 -7.355,-1.817 -7.326,-1.64 -7.279,-1.468 -7.213,-1.302 -7.129,-1.144 -7.029,-0.997 -6.913,-0.86 -6.783,-0.737 -6.641,-0.629 -6.488,-0.537 -6.326,-0.462 -6.156,-0.405 -5.982,-0.367 -5.804,-0.347 -5.626,-0.347 -5.448,-0.367 -5.274,-0.405 -5.104,-0.462 -4.942,-0.537 -4.789,-0.629 -4.647,-0.737 -4.517,-0.86 -4.401,-0.997 -4.301,-1.144 -4.217,-1.302 -4.151,-1.468 -4.104,-1.64 -4.075,-1.817 -4.065,-1.995 -4.075,-2.173 -4.104,-2.35 -4.151,-2.522 -4.217,-2.688 -4.301,-2.846 -4.401,-2.994 -4.517,-3.13 -4.647,-3.253 -4.789,-3.361 -4.942,-3.453 -5.104,-3.528 -5.274,-3.585 -5.448,-3.623 -5.626,-3.643 -5.804,-3.643 -5.982,-3.623 -6.156,-3.585 -6.326,-3.528 -6.488,-3.453 -6.641,-3.361 -6.783,-3.253 -6.913,-3.13 -7.029,-2.994 -7.129,-2.846 -7.213,-2.688 -7.279,-2.522 -7.326,-2.35 -7.355,-2.173
  Board Outline Layer region: 4.065,-1.995 4.228,-1.279 4.686,-0.705 5.348,-0.386 6.082,-0.386 6.744,-0.705 7.202,-1.279 7.365,-1.995 7.365,-1.995 7.202,-2.711 6.744,-3.285 6.082,-3.604 5.348,-3.604 4.686,-3.285 4.228,-2.711 4.065,-1.995
  Board Outline Layer region: 4.065,-1.995 4.075,-1.817 4.104,-1.64 4.151,-1.468 4.217,-1.302 4.301,-1.144 4.401,-0.997 4.517,-0.86 4.647,-0.737 4.789,-0.629 4.942,-0.537 5.104,-0.462 5.274,-0.405 5.448,-0.367 5.626,-0.347 5.804,-0.347 5.982,-0.367 6.156,-0.405 6.326,-0.462 6.488,-0.537 6.641,-0.629 6.783,-0.737 6.913,-0.86 7.029,-0.997 7.129,-1.144 7.213,-1.302 7.279,-1.468 7.326,-1.64 7.355,-1.817 7.365,-1.995 7.355,-2.173 7.326,-2.35 7.279,-2.522 7.213,-2.688 7.129,-2.846 7.029,-2.994 6.913,-3.13 6.783,-3.253 6.641,-3.361 6.488,-3.453 6.326,-3.528 6.156,-3.585 5.982,-3.623 5.804,-3.643 5.626,-3.643 5.448,-3.623 5.274,-3.585 5.104,-3.528 4.942,-3.453 4.789,-3.361 4.647,-3.253 4.517,-3.13 4.401,-2.994 4.301,-2.846 4.217,-2.688 4.151,-2.522 4.104,-2.35 4.075,-2.173
  Multi-Layer board cut-out: -7.365,-1.995 -7.202,-1.279 -6.744,-0.705 -6.082,-0.386 -5.348,-0.386 -4.686,-0.705 -4.228,-1.279 -4.065,-1.995 -4.065,-1.995 -4.228,-2.711 -4.686,-3.285 -5.348,-3.604 -6.082,-3.604 -6.744,-3.285 -7.202,-2.711 -7.365,-1.995
  Multi-Layer board cut-out: 4.065,-1.995 4.228,-1.279 4.686,-0.705 5.348,-0.386 6.082,-0.386 6.744,-0.705 7.202,-1.279 7.365,-1.995 7.365,-1.995 7.202,-2.711 6.744,-3.285 6.082,-3.604 5.348,-3.604 4.686,-3.285 4.228,-2.711 4.065,-1.995
  silkscreen extent -8.05,-12.92 8.05,8.68
SOD-323_L1.8-W1.3-LS2.5-RD [mm]
  rect 1x0.7 smd: 1(-1.172,0) 2(1.172,0)
  silkscreen extent -1.08,-0.8 0.9,0.8
SOT-23-3_L2.9-W1.6-P1.90-LS2.8-BR [mm]
  rect 1.07x0.6 smd: 1(1.235,-0.95) 2(1.235,0.95) 3(-1.235,0)
  silkscreen extent -0.88,-1.54 0.88,1.54
SOT-23-5_L3.0-W1.7-P0.95-LS2.8-BL [mm]
  rect 0.49x1.157 smd: 1(-0.95,-1.154) 2(0,-1.154) 3(0.95,-1.154)
  rect 0.49x1.175 smd: 4(0.95,1.154) 5(-0.95,1.154)
  silkscreen extent -1.8,-1.29 1.53,0.85
SOT-23-6_L2.9-W1.6-P0.95-LS2.8-BR [mm]
  rect 1.1x0.6 smd paste+0 mask+0.051: 1(1.35,-0.95) 2(1.35,0) 3(1.35,0.95) 4(-1.35,0.95) 5(-1.35,0) 6(-1.35,-0.95)
  silkscreen extent -0.9,-1.78 1.52,1.55
SW-SMD_4P-L4.2-W3.3-P2.15-LS5.1 [mm]
  rect 1.3x0.7 smd: 1(-2.25,1.075) 2(2.25,1.075) 3(-2.25,-1.075) 4(2.25,-1.075)
  silkscreen extent -2.1,-1.7 2.1,1.7
TF-SMD_TF-PUSH [mm]
  rect 0.7x1.6 smd: 1(2.25,5.3) 2(1.15,5.3) 3(0.05,5.3) 4(-1.05,5.3) 5(-2.15,5.3) 6(-3.25,5.3) 7(-4.35,5.3) 8(-5.45,5.3) CD(-6.55,5.3)
  rect 1.2x1.5 smd: 10(-7.75,4.3)
  rect 1.2x2.2 smd: 11(-7.75,-5.3) 12(7.75,-5.3)
  rect 1.6x1.5 smd: 13(6.85,4.3)
  Board Outline Layer circle w0.003: c-4.95,-5.7 r0.6
  Board Outline Layer circle w0.003: c3.05,-5.7 r0.6
  Board Outline Layer region: -5.55,-5.7 -5.491,-5.44 -5.324,-5.231 -5.083,-5.115 -4.816,-5.115 -4.576,-5.231 -4.409,-5.44 -4.35,-5.7 -4.35,-5.7 -4.409,-5.96 -4.576,-6.169 -4.816,-6.285 -5.083,-6.285 -5.324,-6.169 -5.491,-5.96 -5.55,-5.7
  Board Outline Layer region: -5.55,-5.7 -5.541,-5.596 -5.514,-5.495 -5.47,-5.4 -5.41,-5.314 -5.336,-5.24 -5.25,-5.18 -5.155,-5.136 -5.054,-5.109 -4.95,-5.1 -4.846,-5.109 -4.745,-5.136 -4.65,-5.18 -4.564,-5.24 -4.49,-5.314 -4.43,-5.4 -4.386,-5.495 -4.359,-5.596 -4.35,-5.7 -4.359,-5.804 -4.386,-5.905 -4.43,-6 -4.49,-6.086 -4.564,-6.16 -4.65,-6.22 -4.745,-6.264 -4.846,-6.291 -4.95,-6.3 -5.054,-6.291 -5.155,-6.264 -5.25,-6.22 -5.336,-6.16 -5.41,-6.086 -5.47,-6 -5.514,-5.905 -5.541,-5.804
  Board Outline Layer region: 2.45,-5.7 2.509,-5.44 2.676,-5.231 2.917,-5.115 3.184,-5.115 3.424,-5.231 3.591,-5.44 3.65,-5.7 3.65,-5.7 3.591,-5.96 3.424,-6.169 3.184,-6.285 2.917,-6.285 2.676,-6.169 2.509,-5.96 2.45,-5.7
  Board Outline Layer region: 2.45,-5.7 2.459,-5.596 2.486,-5.495 2.53,-5.4 2.59,-5.314 2.664,-5.24 2.75,-5.18 2.845,-5.136 2.946,-5.109 3.05,-5.1 3.154,-5.109 3.255,-5.136 3.35,-5.18 3.436,-5.24 3.51,-5.314 3.57,-5.4 3.614,-5.495 3.641,-5.596 3.65,-5.7 3.641,-5.804 3.614,-5.905 3.57,-6 3.51,-6.086 3.436,-6.16 3.35,-6.22 3.255,-6.264 3.154,-6.291 3.05,-6.3 2.946,-6.291 2.845,-6.264 2.75,-6.22 2.664,-6.16 2.59,-6.086 2.53,-6 2.486,-5.905 2.459,-5.804
  Multi-Layer board cut-out: -5.55,-5.7 -5.491,-5.44 -5.324,-5.231 -5.083,-5.115 -4.816,-5.115 -4.576,-5.231 -4.409,-5.44 -4.35,-5.7 -4.35,-5.7 -4.409,-5.96 -4.576,-6.169 -4.816,-6.285 -5.083,-6.285 -5.324,-6.169 -5.491,-5.96 -5.55,-5.7
  Multi-Layer board cut-out: 2.45,-5.7 2.509,-5.44 2.676,-5.231 2.917,-5.115 3.184,-5.115 3.424,-5.231 3.591,-5.44 3.65,-5.7 3.65,-5.7 3.591,-5.96 3.424,-6.169 3.184,-6.285 2.917,-6.285 2.676,-6.169 2.509,-5.96 2.45,-5.7
  silkscreen extent -7.26,-9.7 8,5.3
USB-A-TH_4P-P1.40-V-F-C39416 [mm]
  round 1.2 hole 0.8: 1(2.098,3.8) 2(0.698,3.8) 3(-0.699,3.8) 4(-2.098,3.8)
  oval 2.1x2.7 hole 1.6 slot 2.1 at 90 deg copper offset -0.001,0.001: 5(-3.08,1.8)
  oval 2.1x2.7 hole 1.6 slot 2.3 at 90 deg copper offset 0.001,0.001: 6(3.08,1.8)
  oval 3x1.8 hole 1.2 slot 2.4 at 0 deg: 7(-0.01,-3.8)
  silkscreen extent -3.5,-8.7 3.5,4.9
USB-A-TH_XUNPU_USB-303WSD-BRY [mm]
  round 1.1 hole 0.7 paste+0 mask+0.05: 1(-3.5,-1.35) 2(-1,-1.35) 3(1,-1.35) 4(3.5,-1.35) 5(4,0.15) 6(2,0.15) 7(0,0.15) 8(-2,0.15) 9(-4,0.15) 10(-3.5,1.85) 11(-1,1.85) 12(1,1.85) 13(3.5,1.85) 14(4,3.35) 15(2,3.35) 16(0,3.35) 17(-2,3.35) 18(-4,3.35)
  round 3.2 hole 2.4 paste+0 mask+0.05: 19(6.57,-3.35) 20(6.57,2.33) 21(-6.57,2.33) 22(-6.57,-3.35)
  silkscreen extent -7.26,-12.97 7.19,4.7
USB-C-SMD_TYPE-C-16PIN-2MD-073 [mm]
  oval 1.1x2 hole 0.6 slot 1.5 at 90 deg paste+0 mask+0.05: 13(-4.325,1.825) 14(4.325,1.825)
  oval 1.2x1.8 hole 0.6 slot 1.2 at 90 deg paste+0 mask+0.05: 13(-4.325,-2.375) 14(4.325,-2.375)
  rect 0.55x1.1 smd paste+0 mask+0.05: A1B12(-3.2,2.375) A4B9(-2.4,2.375) B1A12(3.2,2.375) B4A9(2.4,2.375)
  rect 0.3x1.1 smd paste+0 mask+0.05: A5(-1.25,2.375) A6(-0.25,2.375) A7(0.25,2.375) A8(1.25,2.375) B5(1.75,2.375) B6(0.75,2.375) B7(-0.75,2.375) B8(-1.75,2.375)
  Board Outline Layer circle w0.003: c-2.89,1.305 r0.35
  Board Outline Layer circle w0.003: c2.89,1.305 r0.35
  Board Outline Layer region: -2.89,1.655 -2.738,1.62 -2.616,1.523 -2.549,1.383 -2.549,1.227 -2.616,1.087 -2.738,0.99 -2.89,0.955 -2.89,0.955 -3.042,0.99 -3.164,1.087 -3.231,1.227 -3.231,1.383 -3.164,1.523 -3.042,1.62 -2.89,1.655
  Board Outline Layer region: -2.89,1.655 -2.812,1.646 -2.738,1.62 -2.672,1.579 -2.616,1.523 -2.575,1.457 -2.549,1.383 -2.54,1.305 -2.549,1.227 -2.575,1.153 -2.616,1.087 -2.672,1.031 -2.738,0.99 -2.812,0.964 -2.89,0.955 -2.968,0.964 -3.042,0.99 -3.108,1.031 -3.164,1.087 -3.205,1.153 -3.231,1.227 -3.24,1.305 -3.231,1.383 -3.205,1.457 -3.164,1.523 -3.108,1.579 -3.042,1.62 -2.968,1.646
  Board Outline Layer region: 2.89,1.655 3.042,1.62 3.164,1.523 3.231,1.383 3.231,1.227 3.164,1.087 3.042,0.99 2.89,0.955 2.89,0.955 2.738,0.99 2.616,1.087 2.549,1.227 2.549,1.383 2.616,1.523 2.738,1.62 2.89,1.655
  Board Outline Layer region: 2.89,1.655 2.968,1.646 3.042,1.62 3.108,1.579 3.164,1.523 3.205,1.457 3.231,1.383 3.24,1.305 3.231,1.227 3.205,1.153 3.164,1.087 3.108,1.031 3.042,0.99 2.968,0.964 2.89,0.955 2.812,0.964 2.738,0.99 2.672,1.031 2.616,1.087 2.575,1.153 2.549,1.227 2.54,1.305 2.549,1.383 2.575,1.457 2.616,1.523 2.672,1.579 2.738,1.62 2.812,1.646
  Multi-Layer board cut-out: -2.89,1.655 -2.738,1.62 -2.616,1.523 -2.549,1.383 -2.549,1.227 -2.616,1.087 -2.738,0.99 -2.89,0.955 -2.89,0.955 -3.042,0.99 -3.164,1.087 -3.231,1.227 -3.231,1.383 -3.164,1.523 -3.042,1.62 -2.89,1.655
  Multi-Layer board cut-out: 2.89,1.655 3.042,1.62 3.164,1.523 3.231,1.383 3.231,1.227 3.164,1.087 3.042,0.99 2.89,0.955 2.89,0.955 2.738,0.99 2.616,1.087 2.549,1.227 2.549,1.383 2.616,1.523 2.738,1.62 2.89,1.655
  silkscreen extent -4.5,-4.97 4.57,0.6

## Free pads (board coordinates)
  round 60 smd: 1(330,3236.46) 1(3815,3034.92) 2(3790,386.46) 3(380,141.46) 4(1700,1206.46)
  round 30 smd: 1(385,1011.46) 1(390,1947.63) 1(525,981.35) 1(592.56,1096.46) 1(700,421.46) 1(785,1991.46) 1(885,1726.46) 1(935,1731.46) 1(975,749.58) 1(1065,1526.46) 1(1089.86,1621.46) 1(1137.41,1524.91) 1(1190,1786.46) 1(1440.99,1775.46) 1(1560,1146.46) 1(1655,806.46) 1(2738.27,1306.46) 2(812.63,749.58) 2(2776.36,1366.46) 3(285,1216.46) 4(450.59,1730.64) 5(1371.23,300.22)

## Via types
v1: diameter 16, hole 12, Top Layer to Bottom Layer, 426 vias
v2: diameter 24, hole 12, Top Layer to Bottom Layer, 385 vias
v3: diameter 34, hole 12, Top Layer to Bottom Layer, 2 vias
v4: diameter 30, hole 12, Top Layer to Bottom Layer, 2 vias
